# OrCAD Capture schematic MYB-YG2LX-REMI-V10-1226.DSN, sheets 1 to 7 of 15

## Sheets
1 Cover: title: SCH-MYB-YG2LX-V01; rev: V1.0; note: Cover
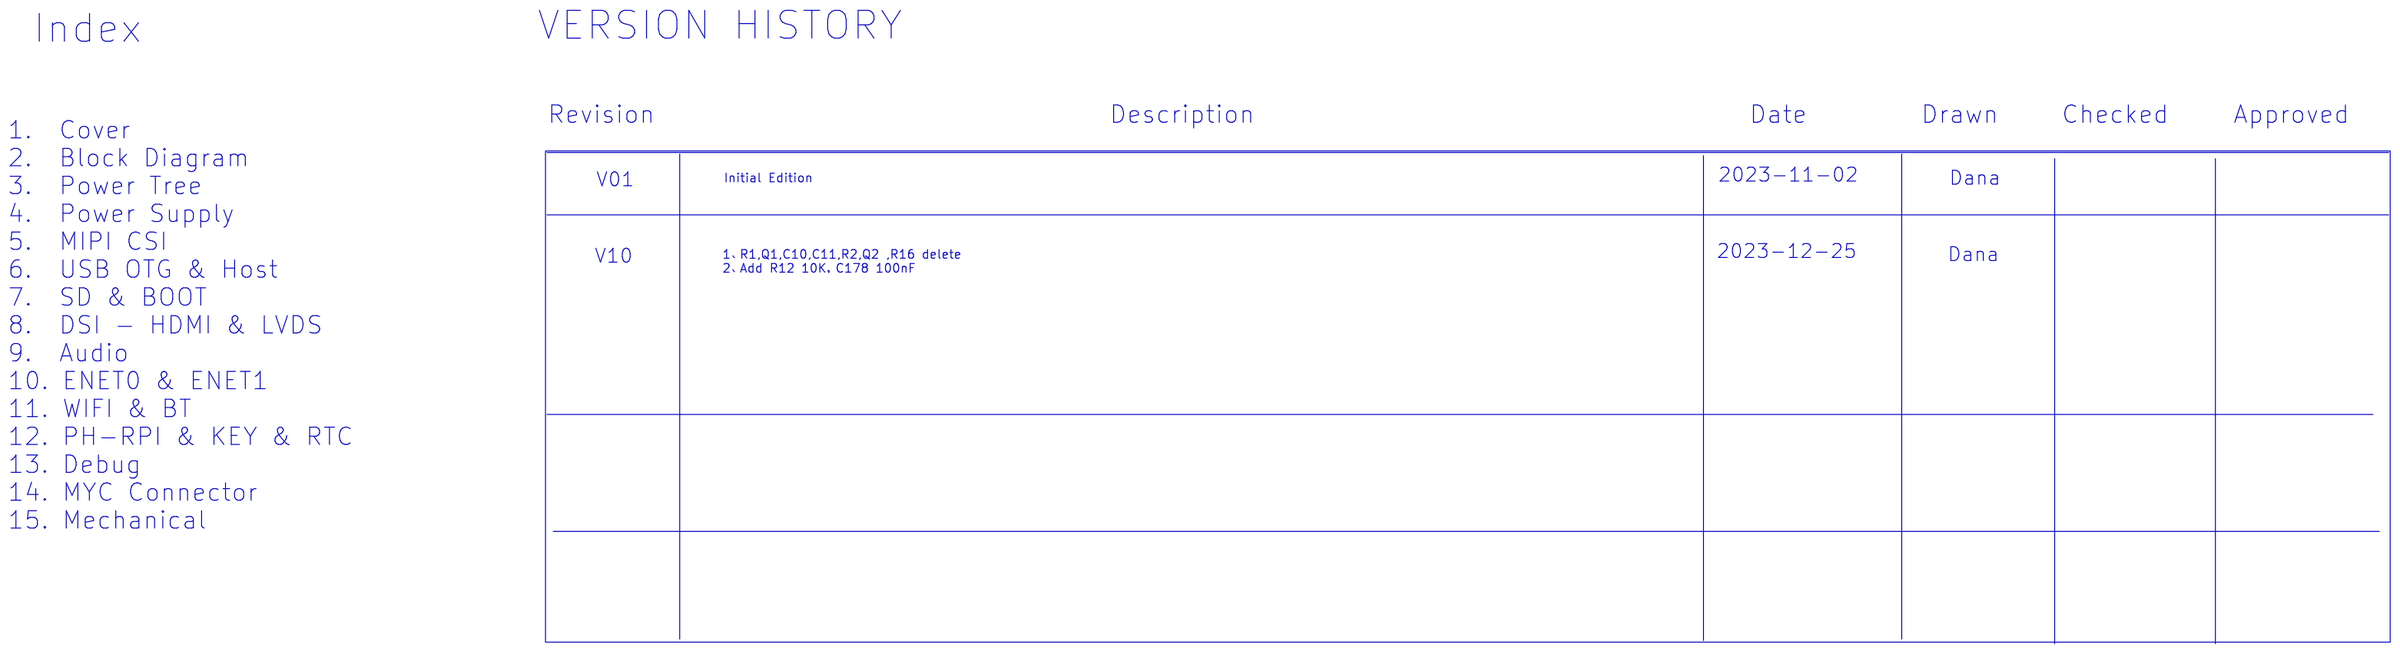
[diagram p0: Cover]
2 Block Diagram: note: Block Diagram
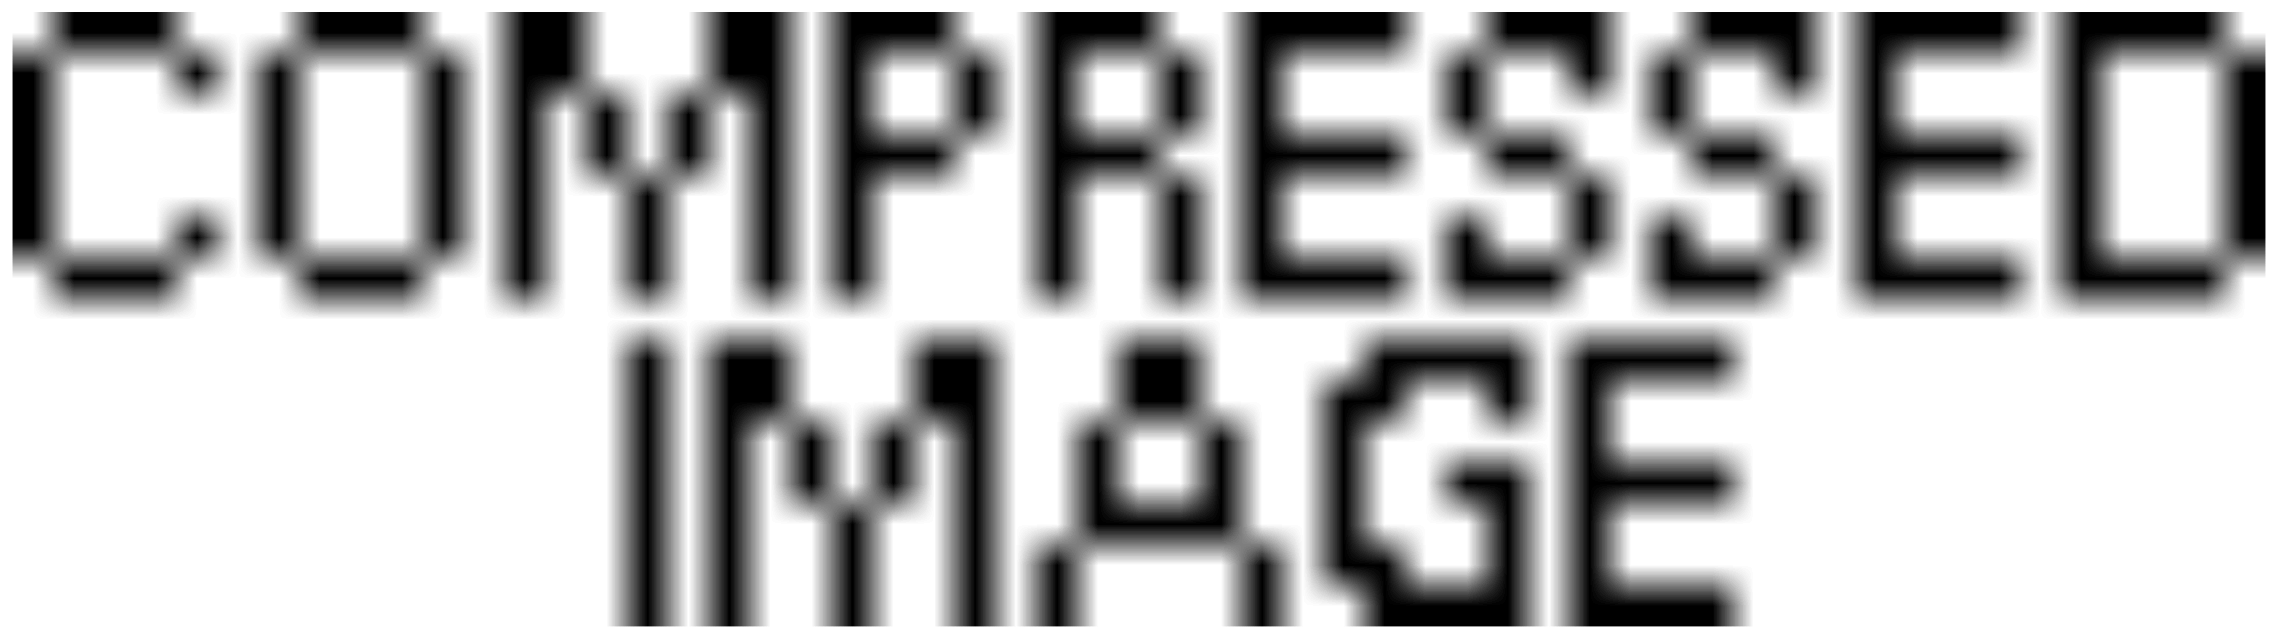
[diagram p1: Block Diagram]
3 Power Tree: note: Power Tree
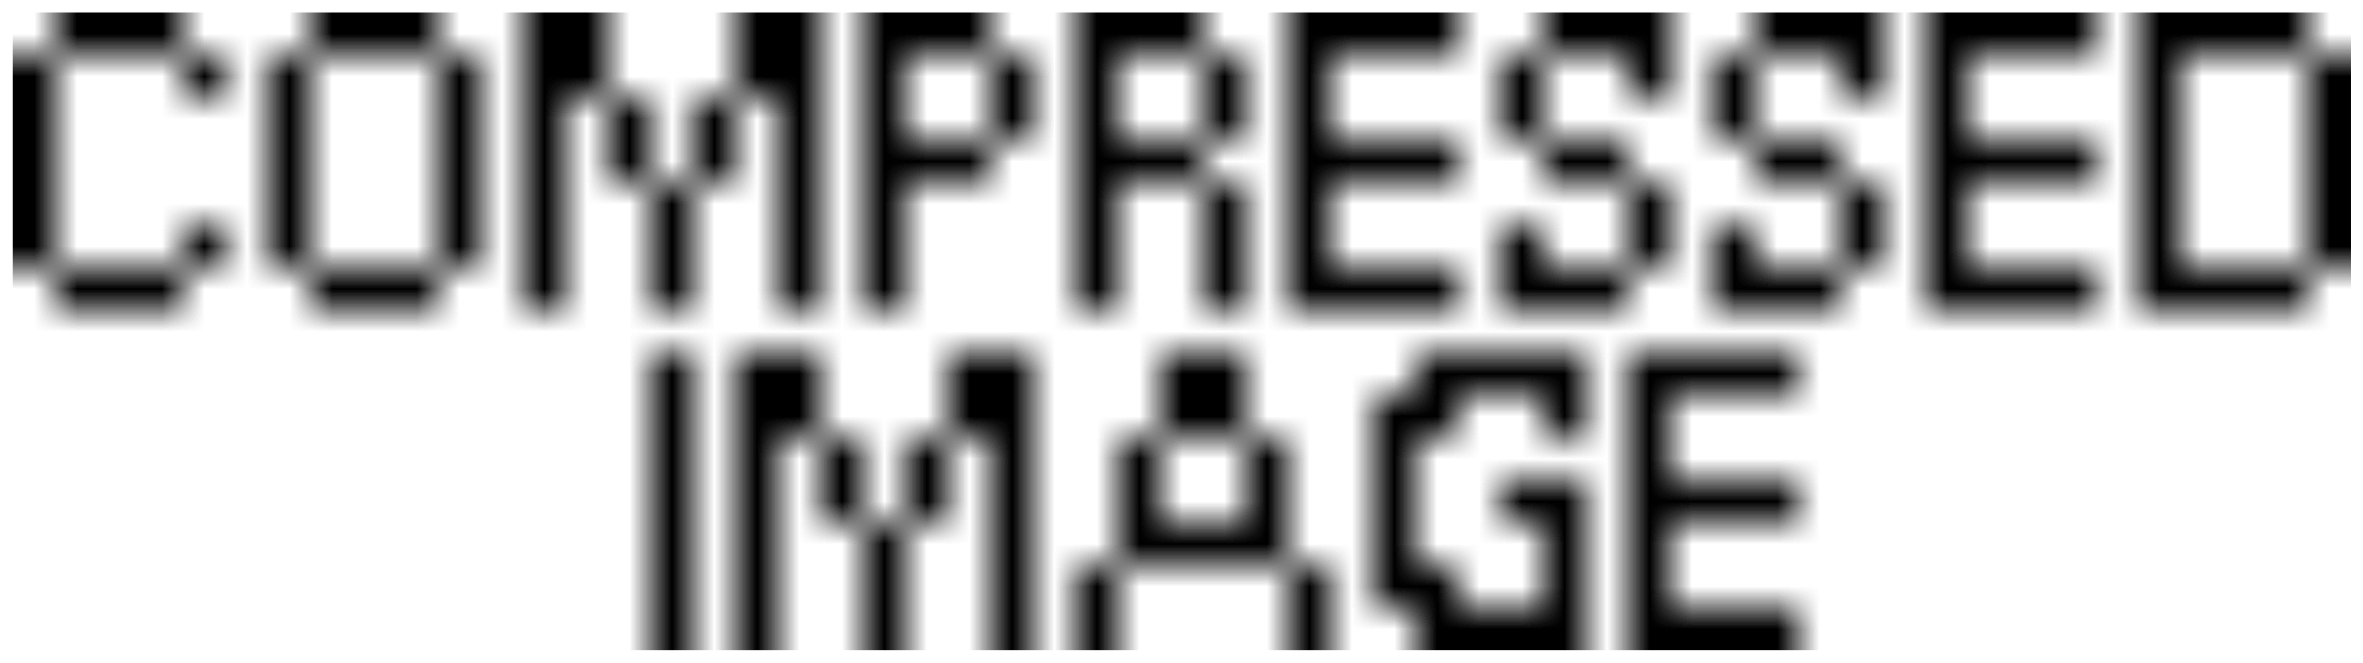
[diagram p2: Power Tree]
4 Power Supply: size A3; note: Power Supply
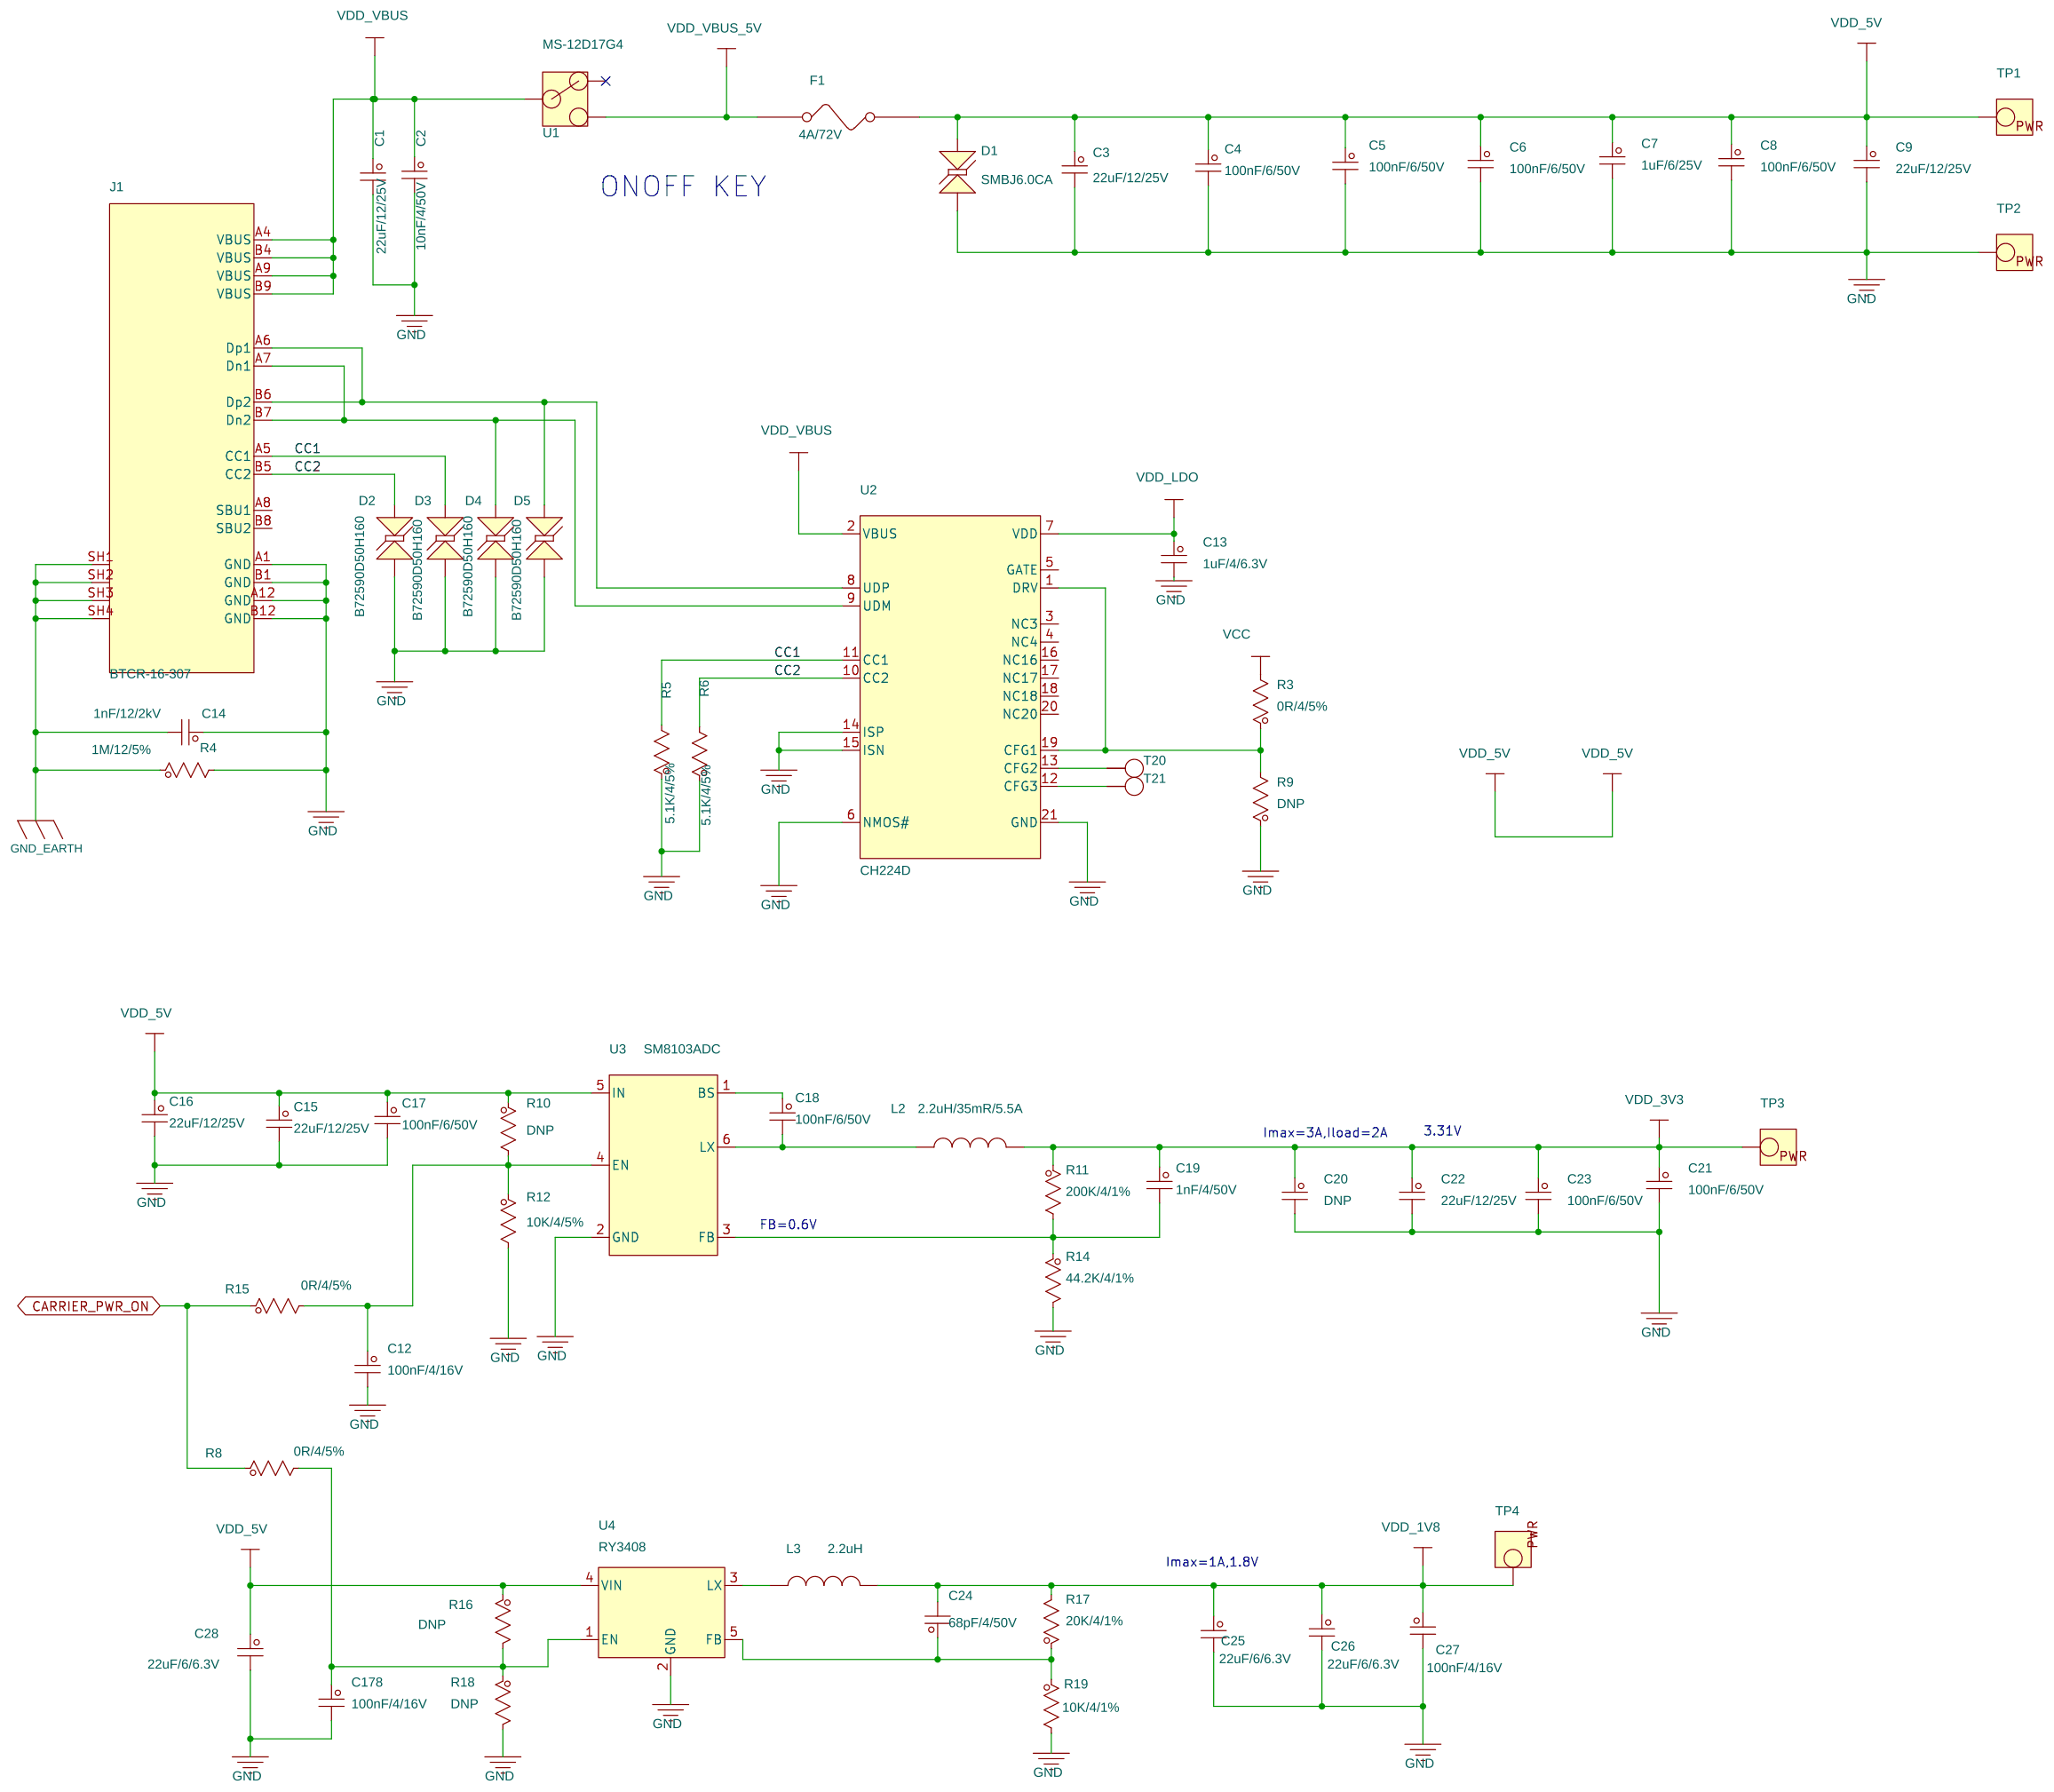
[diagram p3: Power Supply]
5 MIPI-CSI: size A3; note: CSI
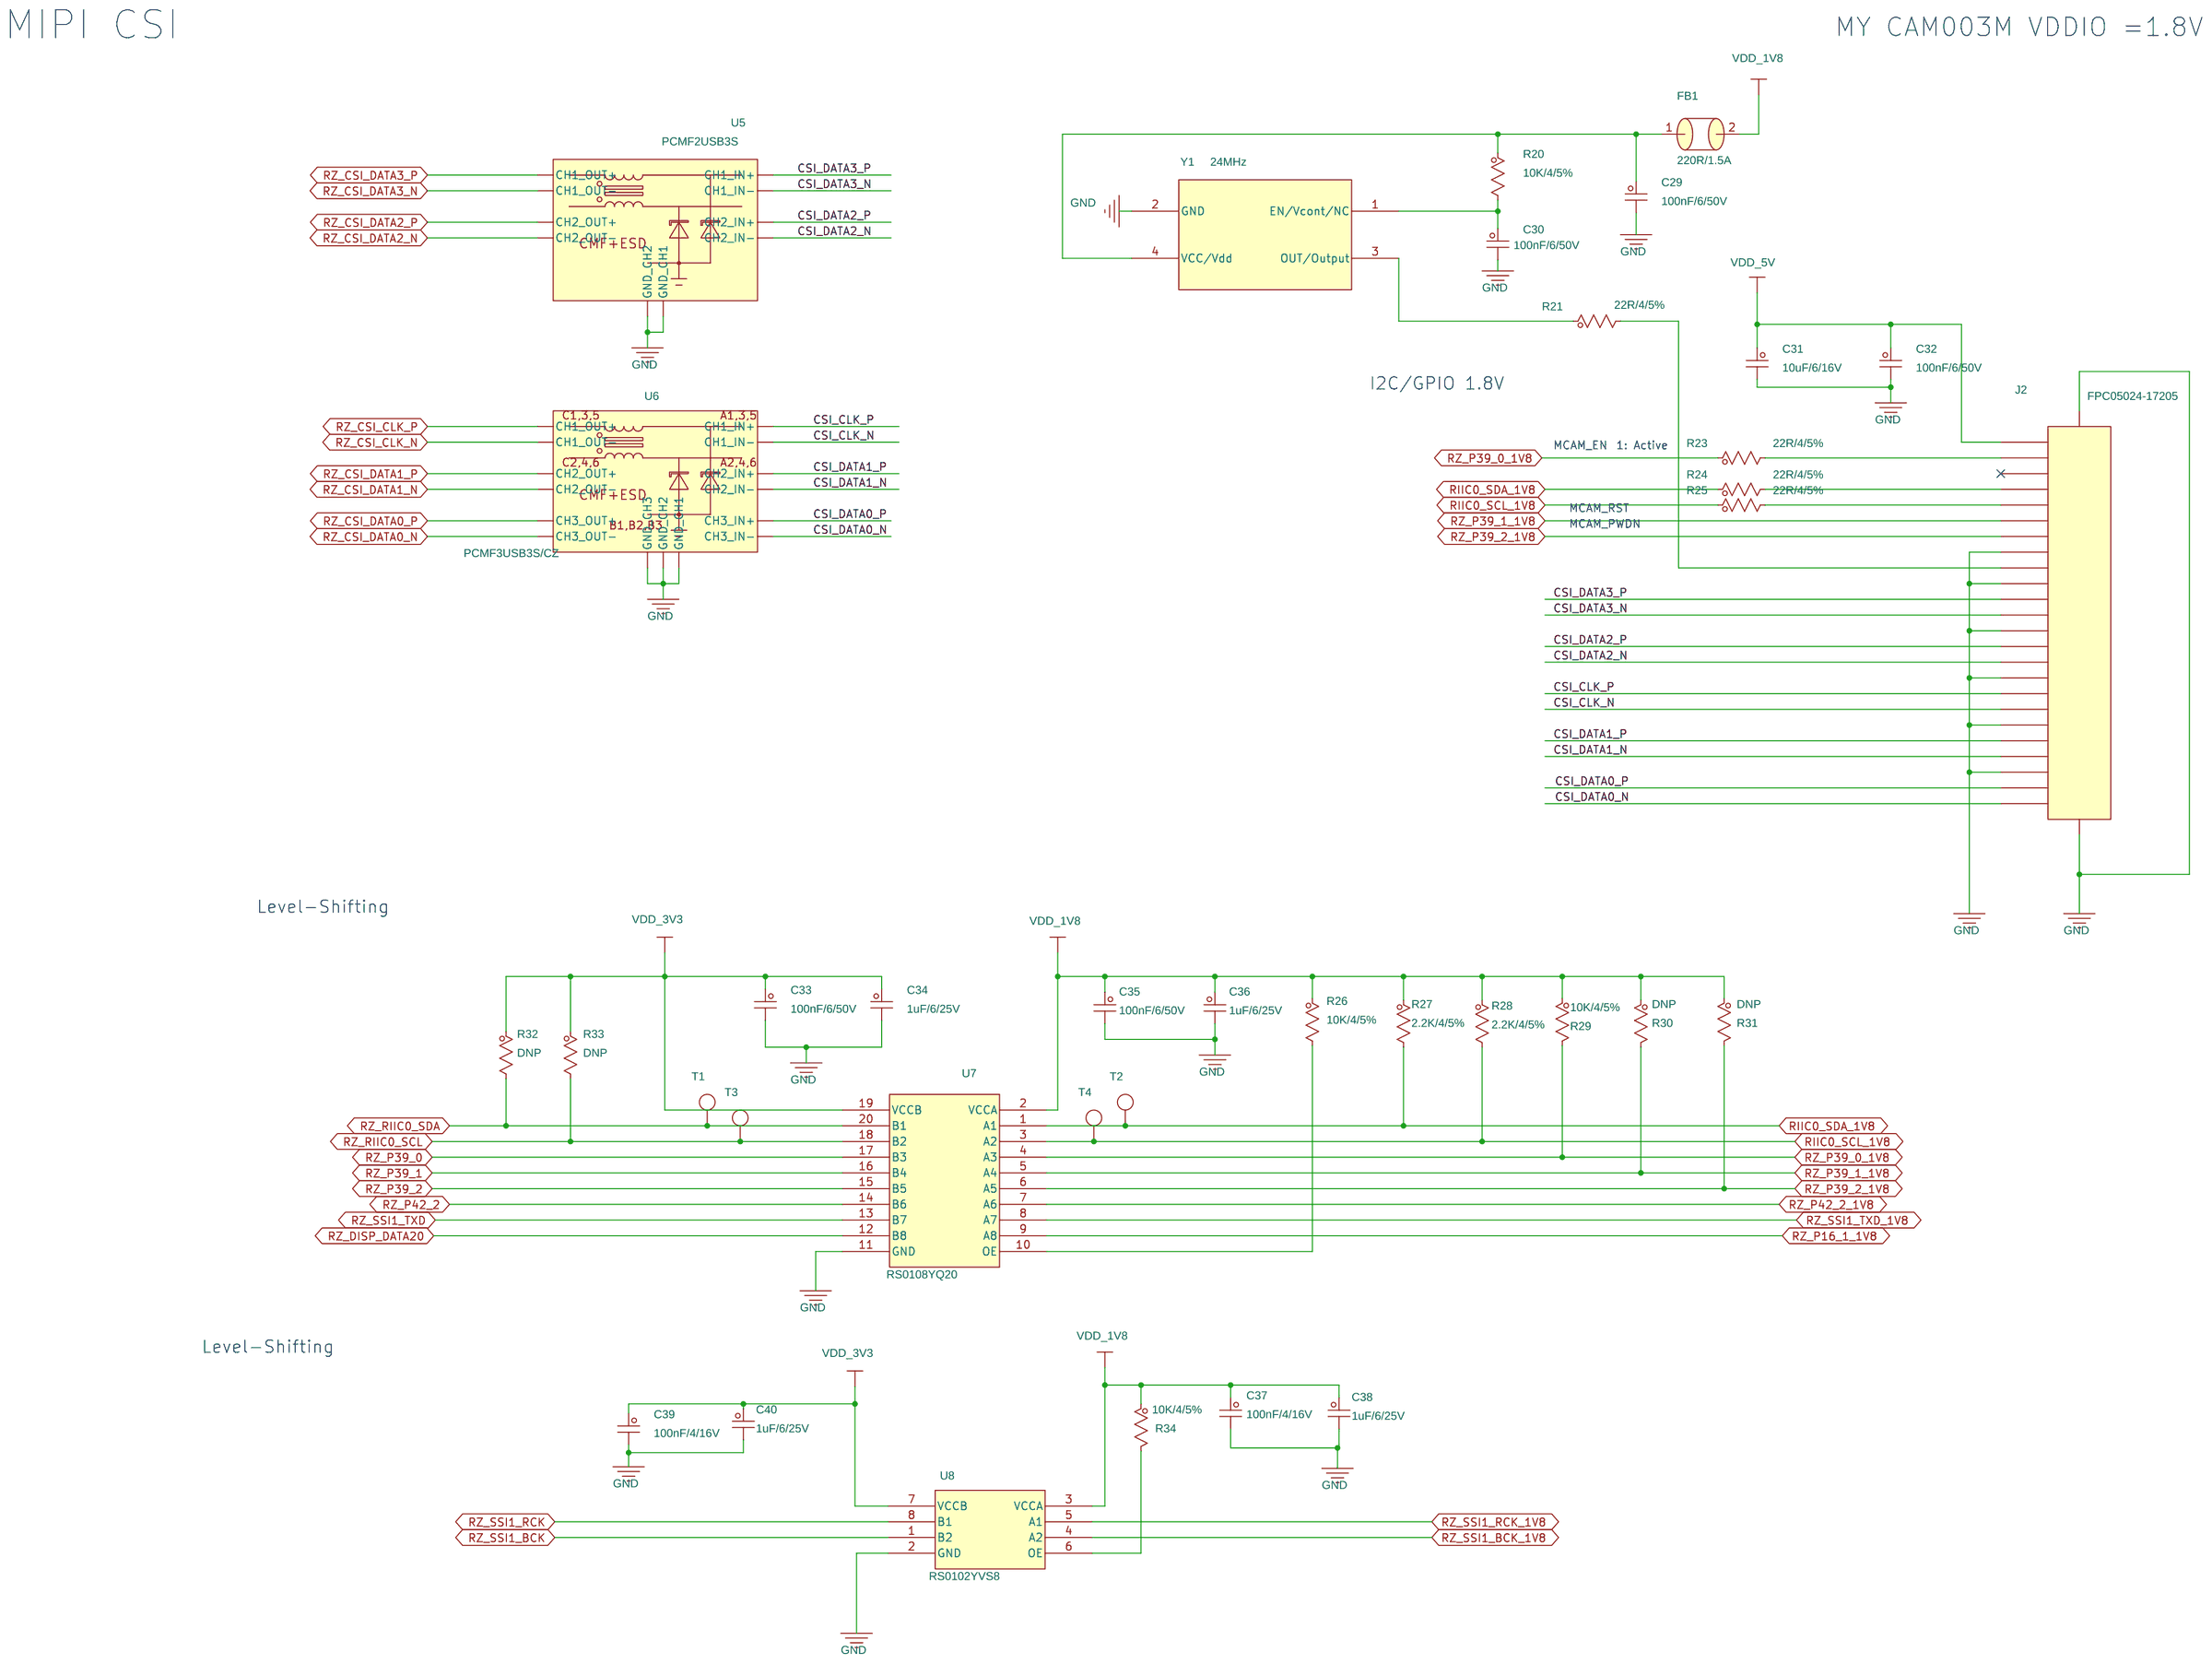
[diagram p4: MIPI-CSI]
6 USB OTG & Host: size A2; note: USB &  Debug
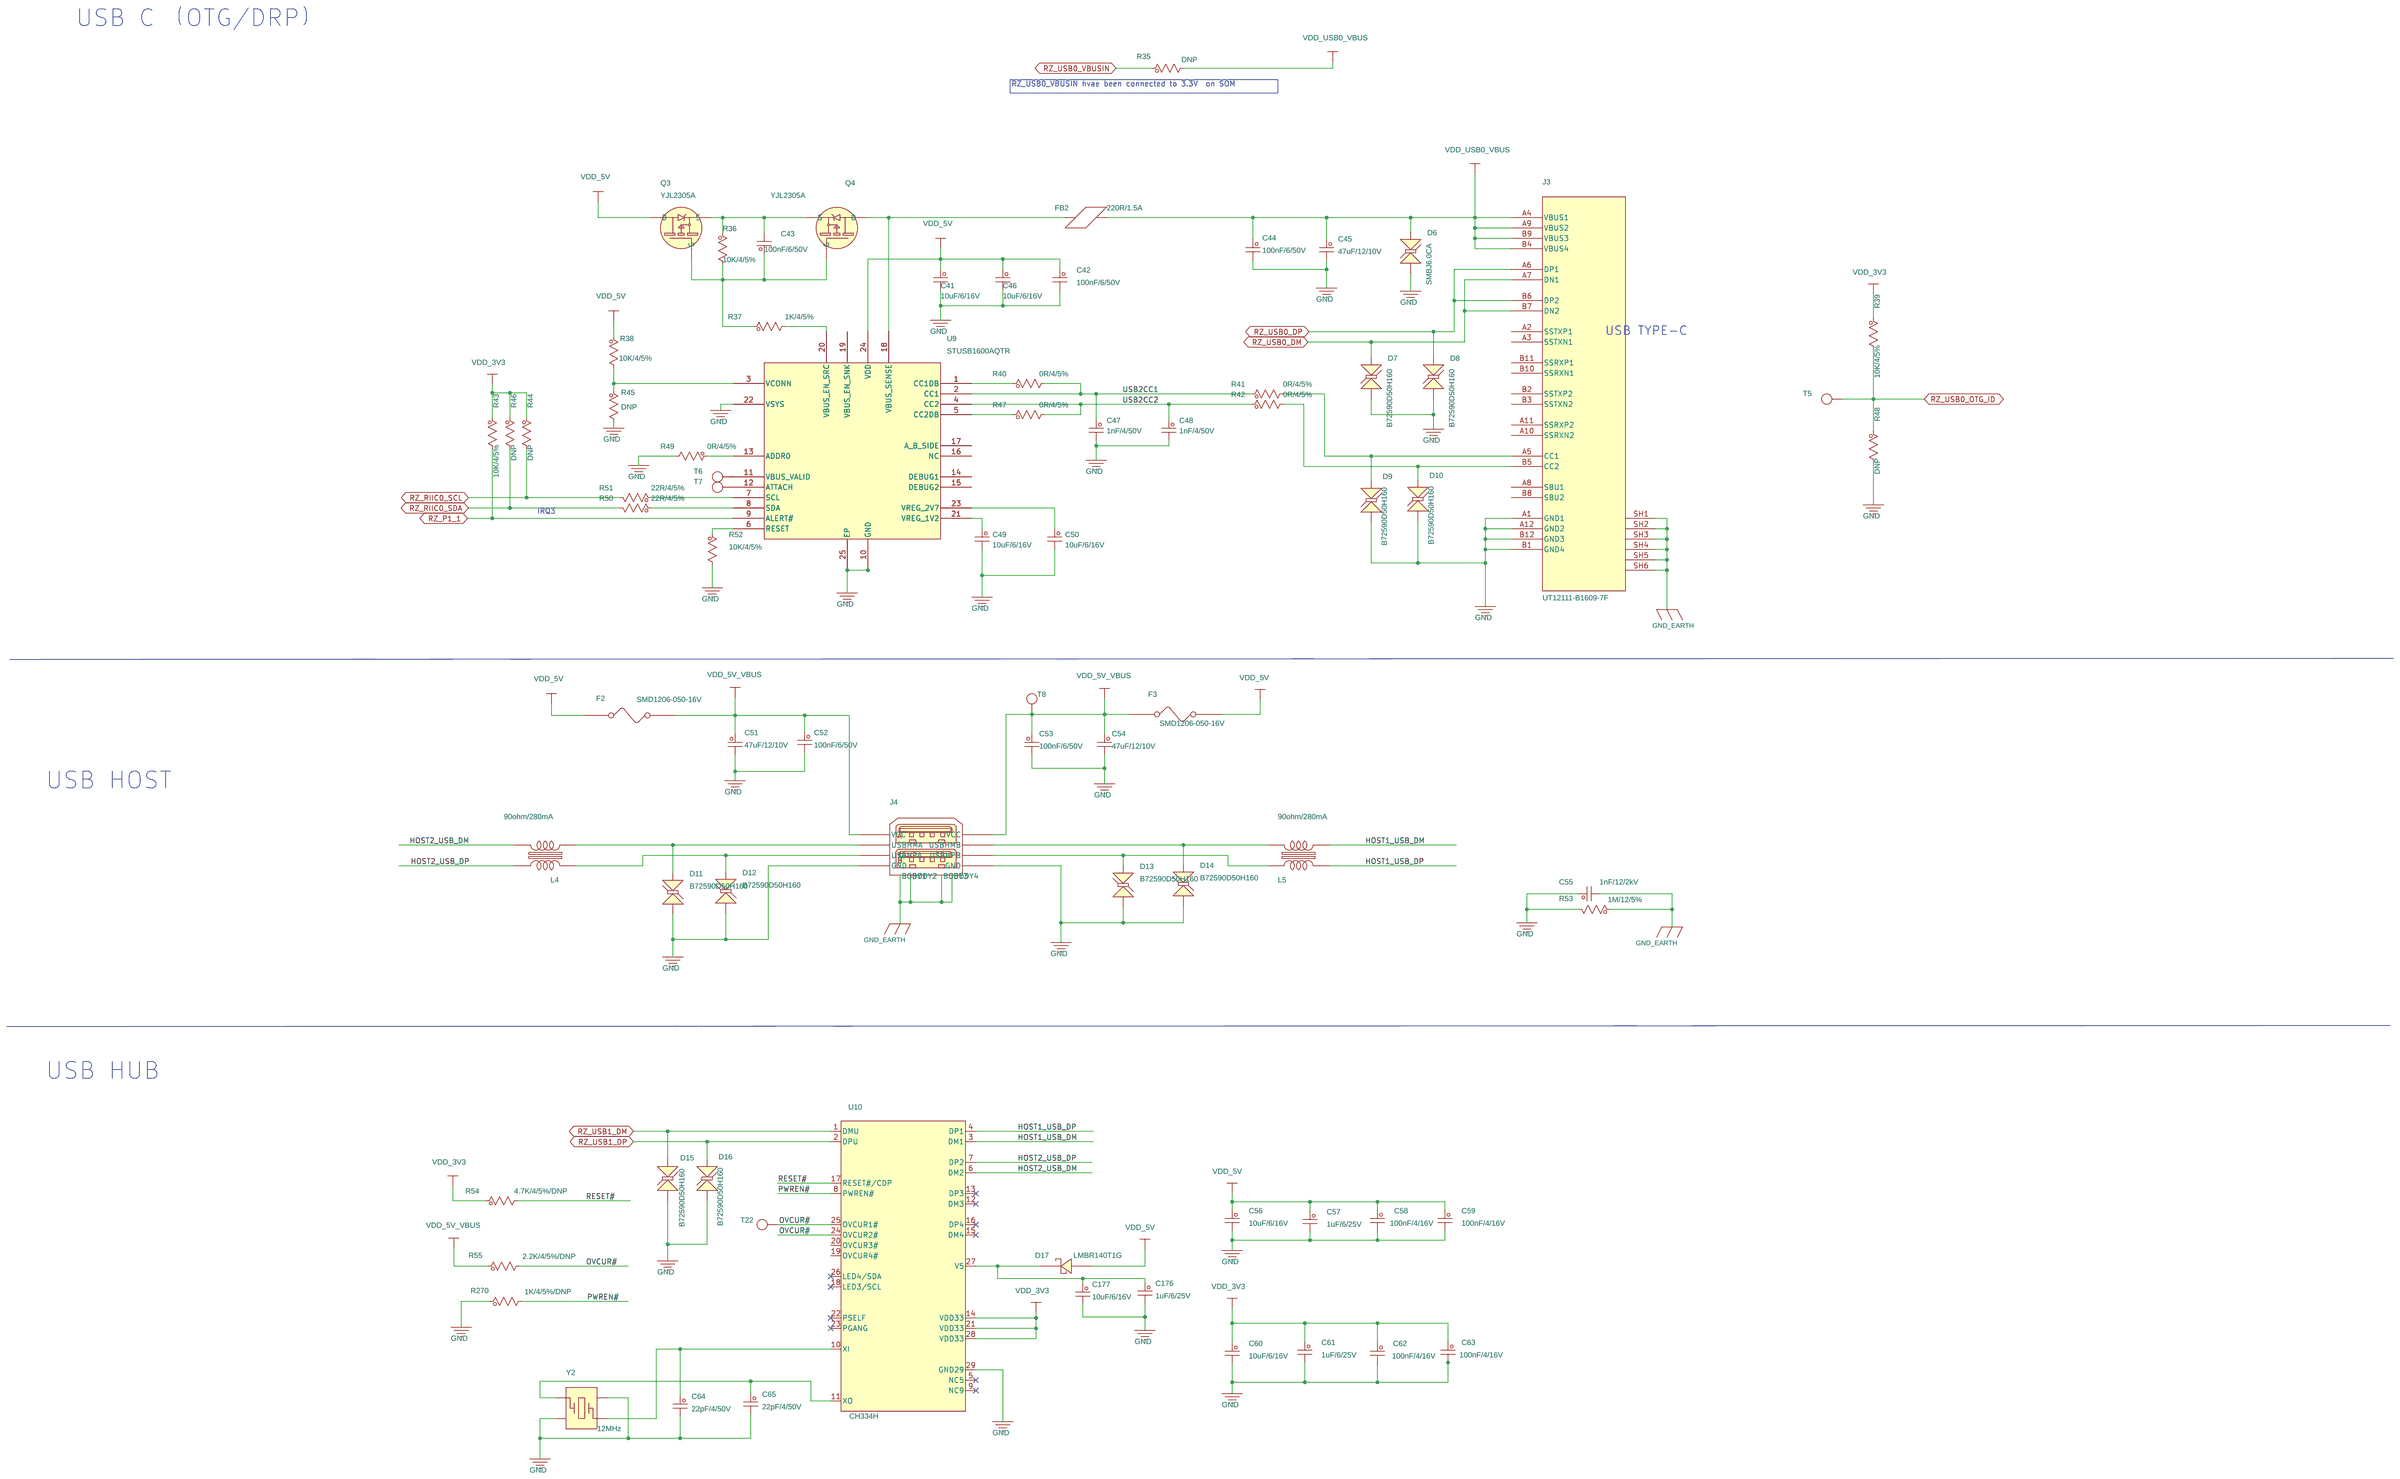
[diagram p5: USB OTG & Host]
7 SD & BOOT: size A3; note: Micro SD & Boot
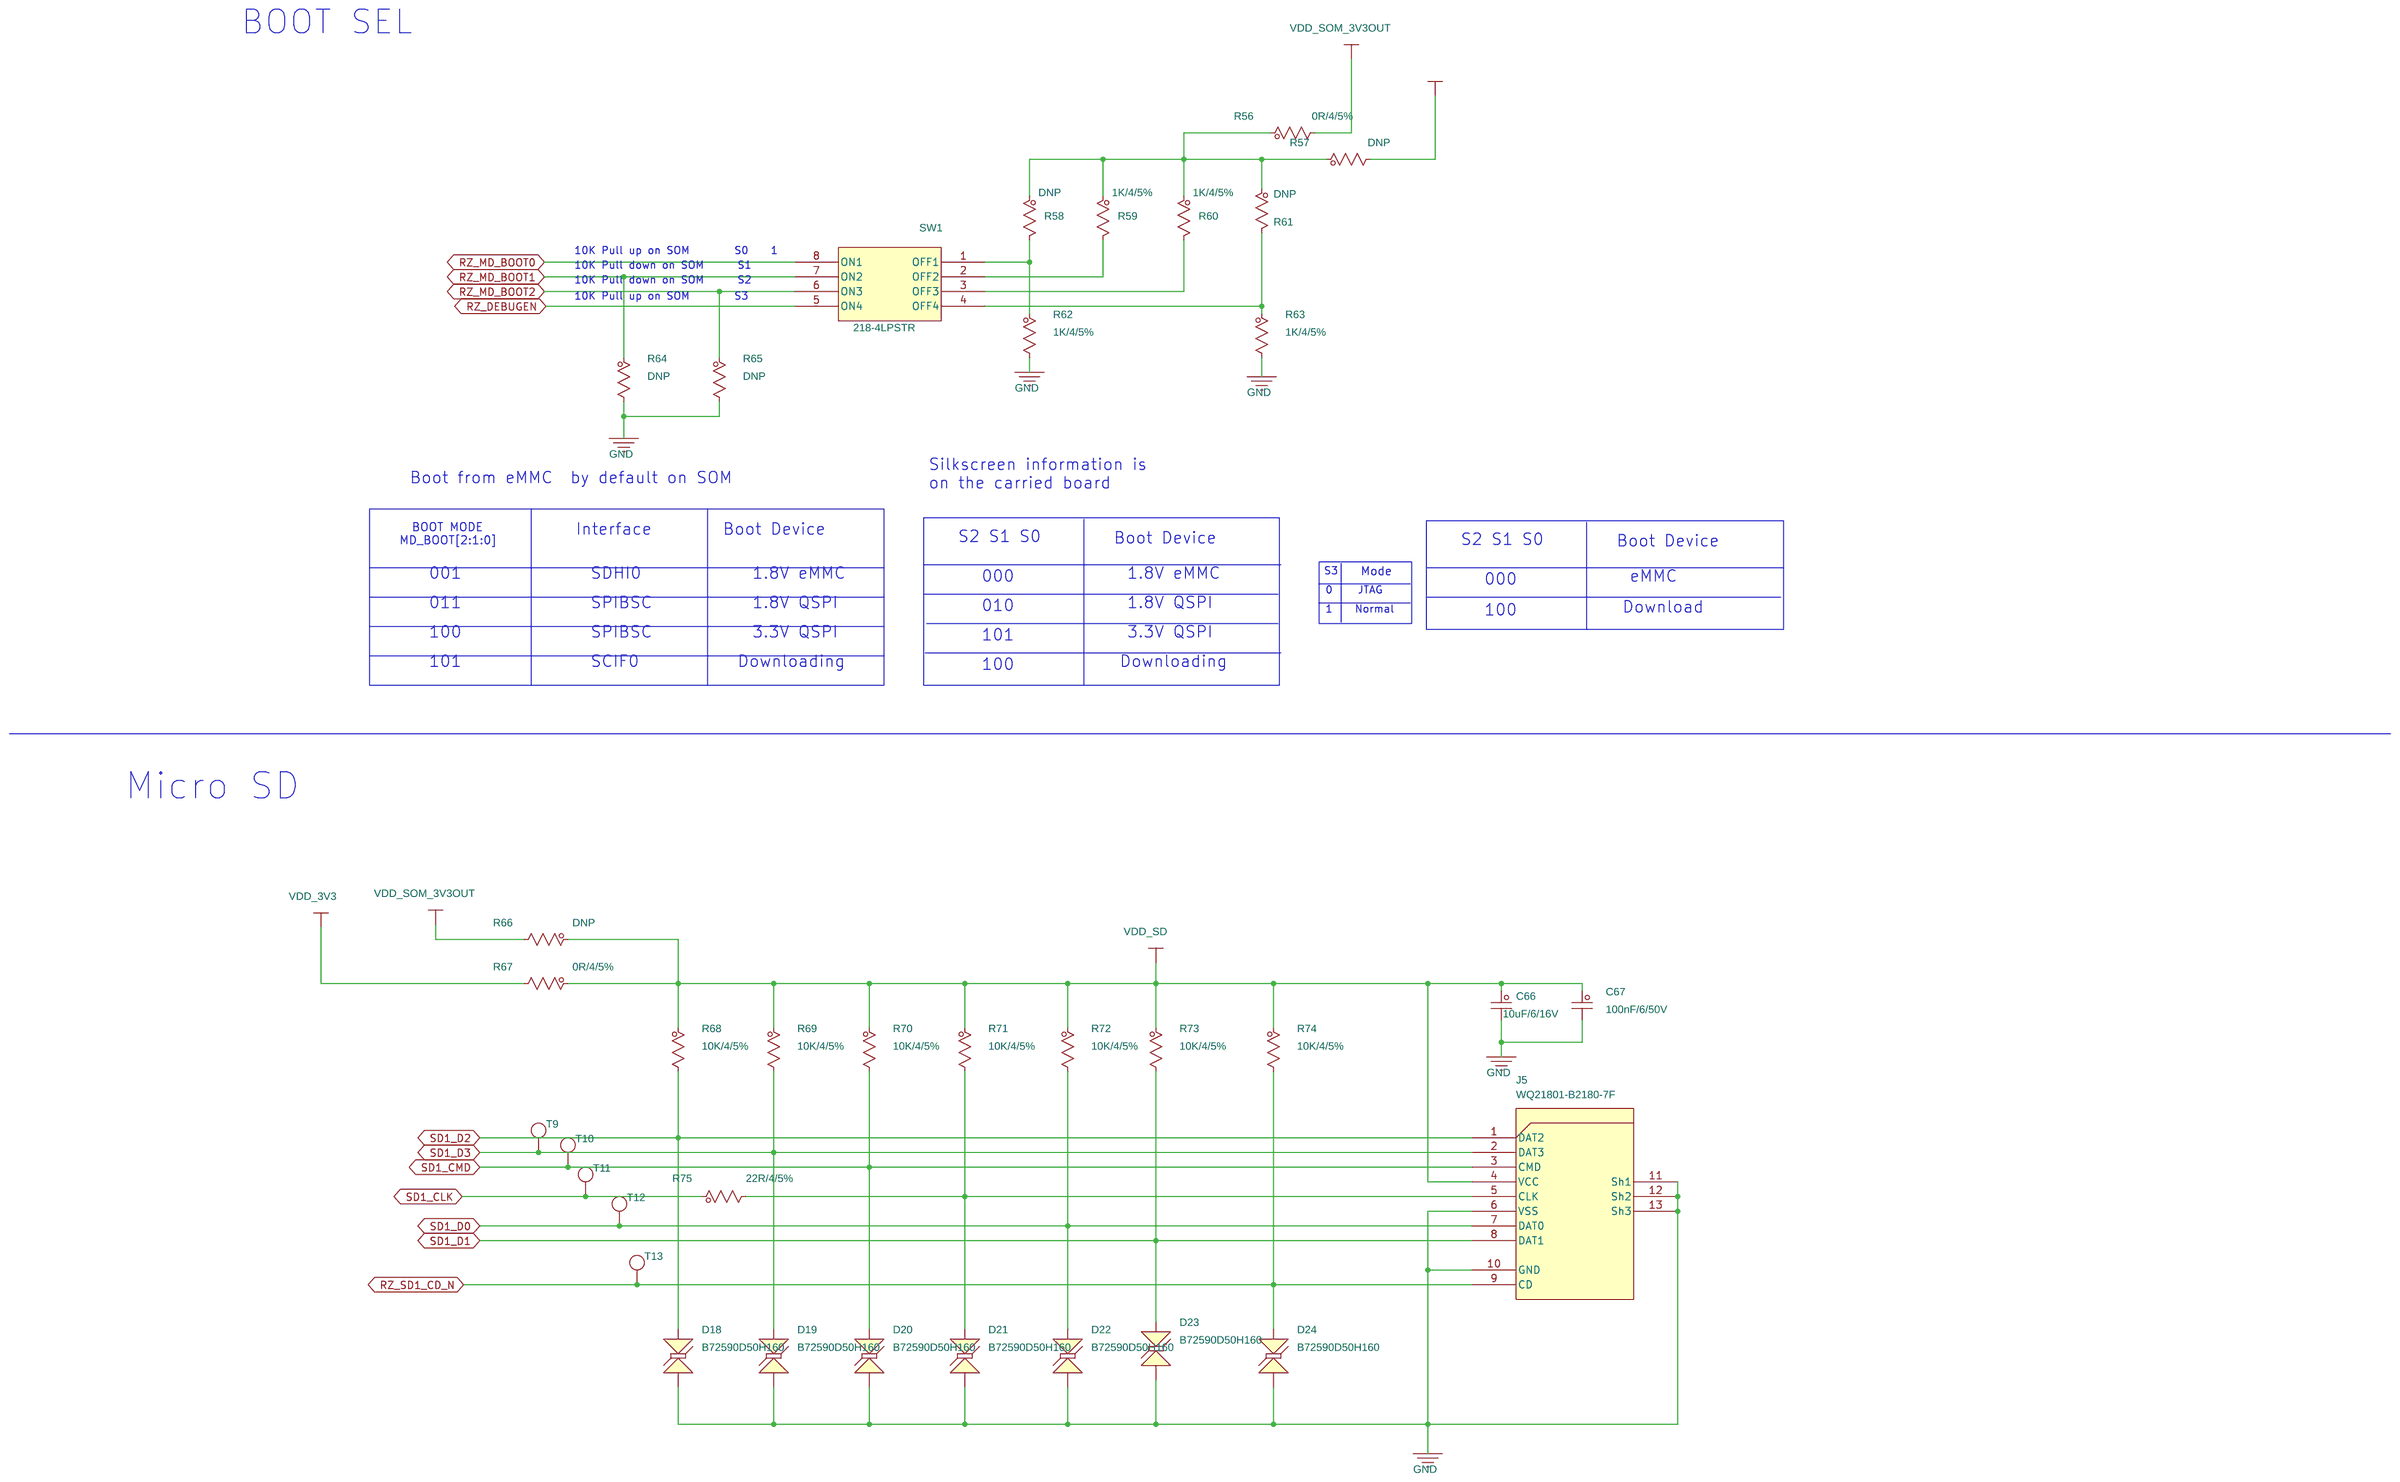
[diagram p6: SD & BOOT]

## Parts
sheet MIPI-CSI
C29  100nF/6/50V  [C0603]
C30  100nF/6/50V  [C0603]
C31  10uF/6/16V  [C0603]
C32  100nF/6/50V  [C0603]
C33  100nF/6/50V  [C0603]
C34  1uF/6/25V  [C0603]
C35  100nF/6/50V  [C0603]
C36  1uF/6/25V  [C0603]
C37  100nF/4/16V  [C0402]
C38  1uF/6/25V  [C0603]
C39  100nF/4/16V  [C0402]
C40  1uF/6/25V  [C0603]
FB1  220R/1.5A  [FB0603]
J2  FPC05024-17205  [FPC24-0_5-h]
R20  10K/4/5%  [R0402]
R21  22R/4/5%  [R0402]
R23  22R/4/5%  [R0402]
R24  22R/4/5%  [R0402]
R25  22R/4/5%  [R0402]
R26  10K/4/5%  [R0402]
R27  2.2K/4/5%  [R0402]
R28  2.2K/4/5%  [R0402]
R29  10K/4/5%  [R0402]
R30  DNP  [R0402]
R31  DNP  [R0402]
R32  DNP  [R0402]
R33  DNP  [R0402]
R34  10K/4/5%  [R0402]
T1  SMD  [test0_8-smd]
T2  SMD  [test0_8-smd]
T3  SMD  [test0_8-smd]
T4  SMD  [test0_8-smd]
U5  PCMF2USB3S  [WLCSP10]
U6  PCMF3USB3S/CZ  [WLCSP15]
U7  RS0108YQ20  [TSSOP20]
U8  RS0102YVS8  [VSSOP8]
Y1  24MHz  [3225]
sheet Power Supply
C1  22uF/12/25V  [C1206]
C2  10nF/4/50V  [C0402]
C3  22uF/12/25V  [C1206]
C4  100nF/6/50V  [C0603]
C5  100nF/6/50V  [C0603]
C6  100nF/6/50V  [C0603]
C7  1uF/6/25V  [C0603]
C8  100nF/6/50V  [C0603]
C9  22uF/12/25V  [C1206]
C12  100nF/4/16V  [C0402]
C13  1uF/4/6.3V  [C0402]
C14  1nF/12/2kV  [C1206]
C15  22uF/12/25V  [C1206]
C16  22uF/12/25V  [C1206]
C17  100nF/6/50V  [C0603]
C18  100nF/6/50V  [C0603]
C19  1nF/4/50V  [C0402]
C20  DNP  [C1206]
C21  100nF/6/50V  [C0603]
C22  22uF/12/25V  [C1206]
C23  100nF/6/50V  [C0603]
C24  68pF/4/50V  [C0402]
C25  22uF/6/6.3V  [C0603]
C26  22uF/6/6.3V  [C0603]
C27  100nF/4/16V  [C0402]
C28  22uF/6/6.3V  [C0603]
C178  100nF/4/16V  [C0402]
D1  SMBJ6.0CA  [DO-214AA]
D2  B72590D50H160  [D0402]
D3  B72590D50H160  [D0402]
D4  B72590D50H160  [D0402]
D5  B72590D50H160  [D0402]
F1  4A/72V  [F1206]
J1  BTCR-16-307  [TYPE-C-BTCF-16-307]
L2  2.2uH/35mR/5.5A  [l5_2x5_5]
L3  2.2uH  [L3X3]
R3  0R/4/5%  [R0402]
R4  1M/12/5%  [R1206]
R5  5.1K/4/5%  [R0402]
R6  5.1K/4/5%  [R0402]
R8  0R/4/5%  [R0402]
R9  DNP  [R0402]
R10  DNP  [R0402]
R11  200K/4/1%  [R0402]
R12  10K/4/5%  [R0402]
R14  44.2K/4/1%  [R0402]
R15  0R/4/5%  [R0402]
R16  DNP  [R0402]
R17  20K/4/1%  [R0402]
R18  DNP  [R0402]
R19  10K/4/1%  [R0402]
T20  SMD  [test0_8-smd]
T21  SMD  [test0_8-smd]
TP1  SMD  [HOLE-TP0_9S16]
TP2  SMD  [HOLE-TP0_9S16]
TP3  SMD  [HOLE-TP0_9S16]
TP4  SMD  [HOLE-TP0_9S16]
U1  MS-12D17G4  [SW-ms-12d17g4]
U2  CH224D  [QFN20-CH224D]
U3  SM8103ADC  [SOT23-6]
U4  RY3408  [tsot23-5]
sheet SD & BOOT
C66  10uF/6/16V  [C0603]
C67  100nF/6/50V  [C0603]
D18  B72590D50H160  [D0402]
D19  B72590D50H160  [D0402]
D20  B72590D50H160  [D0402]
D21  B72590D50H160  [D0402]
D22  B72590D50H160  [D0402]
D23  B72590D50H160  [D0402]
D24  B72590D50H160  [D0402]
J5  WQ21801-B2180-7F  [WQ21801-B2180-7F]
R56  0R/4/5%  [R0402]
R57  DNP  [R0402]
R58  DNP  [R0402]
R59  1K/4/5%  [R0402]
R60  1K/4/5%  [R0402]
R61  DNP  [R0402]
R62  1K/4/5%  [R0402]
R63  1K/4/5%  [R0402]
R64  DNP  [R0402]
R65  DNP  [R0402]
R66  DNP  [R0402]
R67  0R/4/5%  [R0402]
R68  10K/4/5%  [R0402]
R69  10K/4/5%  [R0402]
R70  10K/4/5%  [R0402]
R71  10K/4/5%  [R0402]
R72  10K/4/5%  [R0402]
R73  10K/4/5%  [R0402]
R74  10K/4/5%  [R0402]
R75  22R/4/5%  [R0402]
SW1  218-4LPSTR  [sw-2x4]
T9  SMD  [test0_8-smd]
T10  SMD  [test0_8-smd]
T11  SMD  [test0_8-smd]
T12  SMD  [test0_8-smd]
T13  SMD  [test0_8-smd]
sheet USB OTG & Host
C41  10uF/6/16V  [C0603]
C42  100nF/6/50V  [C0603]
C43  100nF/6/50V  [C0603]
C44  100nF/6/50V  [C0603]
C45  47uF/12/10V  [C1206]
C46  10uF/6/16V  [C0603]
C47  1nF/4/50V  [C0402]
C48  1nF/4/50V  [C0402]
C49  10uF/6/16V  [C0603]
C50  10uF/6/16V  [C0603]
C51  47uF/12/10V  [C1206]
C52  100nF/6/50V  [C0603]
C53  100nF/6/50V  [C0603]
C54  47uF/12/10V  [C1206]
C55  1nF/12/2kV  [C1206]
C56  10uF/6/16V  [C0603]
C57  1uF/6/25V  [C0603]
C58  100nF/4/16V  [C0402]
C59  100nF/4/16V  [C0402]
C60  10uF/6/16V  [C0603]
C61  1uF/6/25V  [C0603]
C62  100nF/4/16V  [C0402]
C63  100nF/4/16V  [C0402]
C64  22pF/4/50V  [C0402]
C65  22pF/4/50V  [C0402]
C176  1uF/6/25V  [C0603]
C177  10uF/6/16V  [C0603]
D6  SMBJ6.0CA  [do-214aa]
D7  B72590D50H160  [D0402]
D8  B72590D50H160  [D0402]
D9  B72590D50H160  [D0402]
D10  B72590D50H160  [D0402]
D11  B72590D50H160  [D0402]
D12  B72590D50H160  [D0402]
D13  B72590D50H160  [D0402]
D14  B72590D50H160  [D0402]
D15  B72590D50H160  [D0402]
D16  B72590D50H160  [D0402]
D17  LMBR140T1G  [SOD123]
F2  SMD1206-050-16V  [F1206]
F3  SMD1206-050-16V  [F1206]
FB2  220R/1.5A  [FB0603]
J3  UT12111-B1609-7F  [UT12111-B1609-7F]
J4  UB11121-8FDE-4F  [UB11121-8FDE-4F]
L4  90ohm/280mA  [indcm-sdcw2012]
L5  90ohm/280mA  [indcm-sdcw2012]
Q3  YJL2305A  [SOT-23]
Q4  YJL2305A  [SOT-23]
R35  DNP  [R0402]
R36  10K/4/5%  [R0402]
R37  1K/4/5%  [R0402]
R38  10K/4/5%  [R0402]
R39  10K/4/5%  [R0402]
R40  0R/4/5%  [R0402]
R41  0R/4/5%  [R0402]
R42  0R/4/5%  [R0402]
R43  10K/4/5%  [R0402]
R44  DNP  [R0402]
R45  DNP  [R0402]
R46  DNP  [R0402]
R47  0R/4/5%  [R0402]
R48  DNP  [R0402]
R49  0R/4/5%  [R0402]
R50  22R/4/5%  [R0402]
R51  22R/4/5%  [R0402]
R52  10K/4/5%  [R0402]
R53  1M/12/5%  [R1206]
R54  4.7K/4/5%/DNP  [R0402]
R55  2.2K/4/5%/DNP  [R0402]
R270  1K/4/5%/DNP  [R0402]
T5  SMD  [test0_8-smd]
T6  SMD  [test0_8-smd]
T7  SMD  [test0_8-smd]
T8  SMD  [test0_8-smd]
T22  SMD  [test0_8-smd]
U9  STUSB1600AQTR  [QFN24]
U10  CH334H  [QFN28_CH334DS]
Y2  12MHz  [3225]

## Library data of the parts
C4-C6 C8 C17 C18 C21 C23 C29 C30 C32 C33 C35 C44 C52 C53 C67 = Ceramic_Capacitor: Ceramic Capacitor,100nF, 50V,+/-10%, X7R,0603,Fenghua; Manufacturer: Fenghua; Manufacturer P/N: 0603B104K500NT; Myir P/N: 20401.80129; Part Type: Ceramic Capacitor; Reserve Value: 100nF; Datasheet: FENGHUA-Capacitor.pdf
C31 C56 C60 C177 = Ceramic_Capacitor: Ceramic Capacitor,10uF,16V,+/-20%,X5R,0603,Samsung; Manufacturer: Samsung; Manufacturer P/N: CL10A106MONQNC; Myir P/N: 20401.80062; Part Type: Ceramic Capacitor; Reserve Value: 10uF; Datasheet: Samsung.pdf
C7 C34 C36 C38 C40 C57 C61 C176 = Ceramic_Capacitor: Ceramic Capacitor,1uF, 25V,+/-10%,X5R,0603,Samsung; Manufacturer: Samsung; Manufacturer P/N: CL10A105KA8NNNC; Myir P/N: 20401.80063; Part Type: Ceramic Capacitor; Reserve Value: 1uF; Datasheet: Samsung.pdf
C12 C27 C37 C39 C178 = Ceramic_Capacitor: Ceramic Capacitor,100nF,16V,+/-10%,X7R,0402,Fenghua; Manufacturer: Fenghua; Manufacturer P/N: 0402B104K160NT; Myir P/N: 20401.80188; Part Type: Ceramic Capacitor; Reserve Value: 100nF; Datasheet: FENGHUA-Capacitor.pdf
FB1 = Ferrite_Bead: Ferrite Bead,220R@100Mhz,1.5A,+/-25%,SMD,0603,Fenghua; Manufacturer: Fenghua; Manufacturer P/N: CBM160808U221T; Myir P/N: 20601.80007; Part Type: Ferrite Bead; Reserve Value: 220R; Datasheet: CBM160808U221T.pdf
J2 = FPC24: FPC Connector,24pin,0.5mm pitch,Dual-sided Contact Models, Operating temperature range from–45~85℃,Atom; Manufacturer: Atom; Myir P/N: 21106.00017; Part Type: FPC Connector; Datasheet: FPC_Atom.pdf
R20 R26 = RESISTER: Thick Film Resistor,10K,+/-5%,1/16W,-55°C ~ 155°C,SMD,0402,Fenghua; Manufacturer: Fenghua; Manufacturer P/N: RC-02W103JT; Myir P/N: 20301.00199; Part Type: Thick Film Resistor; Reserve Value: 10K; Datasheet: FH规格书_2018-07-30.pdf
R21 R23-R25 = RESISTER: Thick Film Resistor,22R,+/-5%,1/16W,-55°C ~ 155°C,SMD,0402,Fenghua; Manufacturer: Fenghua; Manufacturer P/N: RC-02W220JT; Myir P/N: 20301.00187; Part Type: Thick Film Resistor; Reserve Value: 22R; Datasheet: FH规格书_2018-07-30.pdf
R27 R28 R32 R33 = RESISTER: Thick Film Resistor,2.2K,+/-5%,1/16W,-55°C ~ 155°C,SMD,0402,Fenghua; Manufacturer: Fenghua; Manufacturer P/N: RC-02W222JT; Myir P/N: 20301.00195; Part Type: Thick Film Resistor; Reserve Value: 2.2K; Datasheet: FH规格书_2018-07-30.pdf
R29-R31 R34 R58 R61 R68-R74 = Resister: Thick Film Resistor,10K,+/-5%,1/16W,-55°C ~ 155°C,SMD,0402,Fenghua; Manufacturer: Fenghua; Manufacturer P/N: RC-02W103JT; Myir P/N: 20301.00199; Part Type: Thick Film Resistor; Reserve Value: 10K; Datasheet: FHsheet_2018-07-30.PDF
T1-T13 T20-T22 = TP: DESIG: testing PAD; FAB: NA; REF: NA; VAL: NOT POPULATED
U5 = PCMF2USB3S: IC,Common-mode EMI filter for 2 channels with integrated ESD protection,SMD,WLCSP10,PF2S,NXP; Manufacturer: NXP; Myir P/N: 20114.00011; Part Type: Protection; Datasheet: PCMFxUSB3S.pdf
U6 = PCMF3USB3S: IC,Common-mode EMI filter for 3 channels with integrated ESD protection,SMD,WLCSP15,PF3S,NXP; Manufacturer: NXP; Myir P/N: 20114.00010; Part Type: Protection; Datasheet: PCMFxUSB3S.pdf
U7 = TXB0108: IC,8-Bit Bidirectional Voltage-Level Translator for Open-Drain and Push-Pull Applications,SMD,TSSOP20,Runic; Manufacturer: Runic; Myir P/N: 20105.00031; Part Type: Logic; RP1 Manufacturer P/N: TXS0108EPWR; RP1 Myir P/N: 20105.80003; Datasheet: RS0108.pdf
U8 = TXS0102DCT: IC,2-Bit Bidirectional Voltage-Level Translator for Open-Drain and Push-Pull Application,SMD,VSSOP8,Runic; Manufacturer: Runic; Myir P/N: 20105.00030; Part Type: Logic; Datasheet: RS0102.pdf
Y1 = Oscillator_4P: Oscillator,24Mhz,+/- 25ppm,3.3V,-40~85℃,3225,SMD,Hosonic; Manufacturer: Hosonic; Manufacturer P/N: D3SX24E000005E; Myir P/N: 20902.80014; Part Type: Oscillator; Datasheet: 天二电子 201203 D3SX24E000005E V1.0.pdf
C1 = Ceramic_Capacitor: Ceramic Capacitor,22uF,+/-10%,X5R,25V,SMD,1206,Samsung; Manufacturer: Samsung; Manufacturer P/N: CL31A226KAHNNNE; Myir P/N: 20401.00064; Part Type: Ceramic Capacitor; Reserve Value: 22uF; Datasheet: Samsung.pdf
C2 = Ceramic_Capacitor: Ceramic Capacitor,10nF,50V,+/-10%,X7R,0402,Fenghua; Manufacturer: Fenghua; Manufacturer P/N: 0402B103K500NT; Myir P/N: 20401.80103; Part Type: Ceramic Capacitor; Reserve Value: 10nF; Datasheet: FENGHUA-Capacitor.pdf
C3 C9 C15 C16 C22 = Ceramic_Capacitor: Ceramic Capacitor,22uF,25V,+/-10%,X5R,1206,Samsung; Manufacturer: Samsung; Manufacturer P/N: CL31A226KAHNNNE; Myir P/N: 20401.00064; Part Type: Ceramic Capacitor; Reserve Value: 22uF; Datasheet: Samsung.pdf
C13 = Ceramic_Capacitor: Ceramic Capacitor,1uF,6.3V,+/-20%,X5R,SMD,0402,Reel,Fenghua; Manufacturer: Fenghua; Manufacturer P/N: 0402X105M6R3NT; Myir P/N: 20401.00102; Part Type: Ceramic Capacitor; Reserve Value: 1uF; Datasheet: FENGHUA-Capacitor.pdf
C14 = Ceramic_Capacitor: Ceramic Capacitor,1nF,+/-10%,2kV,X7R,SMD,1206,Fenghua; Manufacturer: Fenghua; Manufacturer P/N: 1206B102K202NT; Myir P/N: 20401.00078; Part Type: Ceramic Capacitor; Reserve Value: 1nF; Datasheet: FENGHUA-Capacitor.pdf
C19 = Ceramic_Capacitor: Ceramic Capacitor,1nF,50V,+/-10%,X7R,0402,Fenghua; Manufacturer: Fenghua; Manufacturer P/N: 0402B102K500NT; Myir P/N: 20401.80096; Part Type: Ceramic Capacitor; Reserve Value: 1nF; Datasheet: FENGHUA-Capacitor.pdf
C20 C45 C51 C54 = Ceramic_Capacitor: Ceramic Capacitor,47uF,10V,+/-20%,X5R,1206,Samsung; Manufacturer: Samsung; Manufacturer P/N: CL31A476MPHNNNE; Myir P/N: 20401.80106; Part Type: Ceramic Capacitor; Reserve Value: 47uF; Datasheet: Samsung.pdf
C24 = Ceramic_Capacitor: Ceramic Capacitor,68pF,50V,+/-5%,C0G,0402,Fenghua; Manufacturer: Fenghua; Manufacturer P/N: 0402CG680J500NT; Myir P/N: 20401.80102; Part Type: Ceramic Capacitor; Reserve Value: 68pF; Datasheet: FENGHUA-Capacitor.pdf
C25 C26 C28 = Ceramic_Capacitor: Ceramic Capacitor,22uF,+/-20%,6.3V,X5R,SMD,0603,Samsung; Manufacturer: Samsung; Manufacturer P/N: CL10A226MQ8NRNC; Myir P/N: 20401.00086; Part Type: Ceramic Capacitor; Reserve Value: 22uF; Datasheet: Samsung.pdf
D1 D6 = TVS_Diode: Diode, TVS Bi-Dir 6V 600W, DO-214AA(SMB); Manufacturer: UN; Myir P/N: 20701.00028; Part Type: Diode; Datasheet: SMBJ6.0C.pdf
D2-D5 D7-D16 D18-D24 = TVS_Diode: Diode,TVS,5.6VDC,SMD,D0402,TDK; Manufacturer: TDK; Myir P/N: 20701.00001; Part Type: Diode; Datasheet: B72590D0050H160.pdf
F1 = Fuse: Fuse,Resettable 4A 75V,SMD 1206,TLC; Manufacturer: TLC; Manufacturer P/N: F12F4; Myir P/N: 20801.00014; Part Type: Resettable Fuse; Reserve Value: 4A; Datasheet: F12F Series.pdf
J1 = USB616FC-C2014216: Connector,USB C,16Pin,-25℃~＋85℃,SMD,Reel,GDZ; Manufacturer: GDZ; Myir P/N: 21107.00026; Part Type: USB Connector; Datasheet: BTCF-16-307TYPE-C.pdf
L2 = Inductor: Power Inductor,2.2uH 20%,35mOhm 5.5A ,SMD 5.4*5.2*2.8mm; Manufacturer: Vcoil; Manufacturer P/N: MPH0530-2R2M; Myir P/N: 20501.00020; Part Type: Power Inductor; RP1 Manufacturer P/N: MWSA0503S-2R2MT; RP1 Myir P/N: 20501.00040; Reserve Value: 2.2uH; Datasheet: MPH-Inductor.pdf
L3 = Inductor: Power Inductor,2.2uH,+/-20,SPH,3.0*3.0*1.2mm,SMD,Sunlord; Manufacturer: Sunlord; Manufacturer P/N: SPH3012H2R2MT; Myir P/N: 20501.00034; Part Type: Power Inductor; Datasheet: SPH series of SMD Power Inductor.pdf
R3 R8 = Resister: Thick Film Resistor,0R,+/-5%,1/16W,-55℃~155℃,SMD,0402,Fenghua; Manufacturer: Fenghua; Manufacturer P/N: RC-02000JT; Myir P/N: 20301.00186; Part Type: Thick Film Resistor; Reserve Value: 0R; Datasheet: FHsheet-20230524.pdf
R4 = Resister: Thick Film Resistor,1M,+/-5%,1/4W,-55°C ~ 155°C,SMD,1206,Fenghua; Manufacturer: Fenghua; Manufacturer P/N: RS-06K105JT; Myir P/N: 20301.00226; Part Type: Thick Film Resistor; Reserve Value: 1M; Datasheet: FH规格书_2018-07-30.pdf
R5 R6 = Resister: Thick Film Resistor,5.1K,±5%,1/16W,-55~+155℃,0402,Fenghua; Manufacturer: Fenghua; Manufacturer P/N: RC-02K512JT; Myir P/N: 20301.80358; Part Type: Thick Film Resistor; Reserve Value: 5.1K; Datasheet: FHsheet-20230524.pdf
R9 R12 R18 = Resister: Thick Film Resistor,10K,+/-5%,1/16W,-55℃~155℃,SMD,0402,Fenghua; Manufacturer: Fenghua; Manufacturer P/N: RC-02K103JT; Myir P/N: 20301.00199; Part Type: Thick Film Resistor; Reserve Value: 10K; Datasheet: FHsheet-20230524.pdf
R10 = Resister: Thick Film Resistor,100K,+/-5%,,1/16W,-55°C ~ 155°C,SMD,0402,Fenghua; Manufacturer: Fenghua; Manufacturer P/N: RC-02W104JT; Myir P/N: 20301.00210; Part Type: Thick Film Resistor; Reserve Value: 100K; Datasheet: FH规格书_2018-07-30.pdf
R11 = Resister: Thick Film Resistor,200K,+/- 1%,1/16W,-55°C ~ 155°C,SMD,0402,Fenghua; Manufacturer: Fenghua; Manufacturer P/N: RC-02W2003FT; Myir P/N: 20301.80390; Part Type: Thick Film Resistor; Reserve Value: 200K; Datasheet: FH规格书_2018-07-30.pdf
R14 = Resister: Thick Film Resistor,44.2k,+/-1%,1/16W,-55°C ~ 155°C,SMD,0402,Fenghua; Manufacturer: Fenghua; Manufacturer P/N: RC-02W4422FT; Myir P/N: 20301.00203; Part Type: Thick Film Resistor; Reserve Value: 44.2k; Datasheet: FH规格书_2018-07-30.pdf
R15 R35 R66 R67 = Resister: Thick Film Resistor,0R,+/-5%,1/16W,-55°C ~ 155°C,SMD,0402,Fenghua; Manufacturer: Fenghua; Manufacturer P/N: RC-02000JT; Myir P/N: 20301.00186; Part Type: Thick Film Resistor; Reserve Value: 0R; Datasheet: FHsheet_2018-07-30.PDF
R16 R54 = Resister: Thick Film Resistor,4.7K,+/-5%,1/16W,-55℃~155℃,SMD,0402,Fenghua; Manufacturer: Fenghua; Manufacturer P/N: RC-02K472JT; Myir P/N: 20301.80393; Part Type: Thick Film Resistor; Reserve Value: 4.7K; Datasheet: FHsheet-20230524.pdf
R17 = Resister: Thick Film Resistor,20K,+/-1%,1/16W,-55℃~155℃,SMD,0402,Fenghua; Manufacturer: Fenghua; Manufacturer P/N: RC-02K2002FT; Myir P/N: 20301.00201; Part Type: Thick Film Resistor; Reserve Value: 20K; Datasheet: FHsheet-20230524.pdf
R19 = Resister: Thick Film Resistor,10K,+/-1%,1/16W,-55℃~155℃,SMD,0402,Fenghua; Manufacturer: Fenghua; Manufacturer P/N: RC-02K1002FT; Myir P/N: 20301.80394; Part Type: Thick Film Resistor; Reserve Value: 10K; Datasheet: FHsheet-20230524.pdf
TP1-TP4 = TP_7: DESIG: testing PAD; FAB: NA; REF: NA; VAL: NOT POPULATED
U1 = MS-12D17G4: Switch, Slide Switches 4mm Pitch,3Pin,Straight,black,SMD; Manufacturer: HUANSHENG; Myir P/N: 21203.00006; Part Type: Switch; Datasheet: MS-12D17.pdf
U2 = CH224D: IC,USB PD and other fast charging protocol power receiving chip ch224,QFN20,SMD,WCH; Manufacturer: WCH; Myir P/N: 20115.80094; Part Type: Interface; Datasheet: CH224DS1.PDF
U3 = SM8103ADC: IC,High Efficiency,3.0A,18V Input Synchronous Step Down Regulator,SM8103ADC,SMD,TSOT23-6, Silergy; Manufacturer: Silergy; Myir P/N: 20103.00083; Part Type: Power Management; Datasheet: SM8103ADC.pdf
U4 = RT8059GJ5: IC,2.8V to 5.5V Input,1.5MHZ,1A Output,Step-down DCDC Converter,SMD,TSOT23-5,Rychip; Manufacturer: Rychip; Myir P/N: 20103.00069; Part Type: Power Management; RP1 Myir P/N: 20103.00006; Datasheet: RY3408 Datasheet V1.0.0.pdf
C66 = CERAMIC_CAPACITOR: Ceramic Capacitor,10uF,16V,+/-20%,X5R,0603,Samsung; Manufacturer: Samsung; Manufacturer P/N: CL10A106MONQNC; Myir P/N: 20401.80062; Part Type: Ceramic Capacitor; Reserve Value: 10uF; Datasheet: Samsung.pdf
J5 = WQ21801-B2180-7F: Connector,Micro SD Card,8Pin,gold flash,Black,-25~85℃,SMT,Foxconn; Manufacturer: Foxconn; Mark: 1; Myir P/N: 21112.00009; Part Type: Card Connector; Datasheet: SD_Foxconn_WQ21801-B2180-7F.pdf
R56 R57 = Resister: Thick Film Resistor,0R,+/-5%,1/16W,-55°C ~ 155°C,SMD,0402,Fenghua; Manufacturer: Fenghua; Manufacturer P/N: RC-02000JT; Myir P/N: 20301.00186; Part Type: Thick Film Resistor; Reserve Value: 0R; Datasheet: FH规格书_2018-07-30.pdf
R59 R60 R62 R63 = Resister: Thick Film Resistor,1K,+/-5%,1/16W,-55°C ~ 155°C,SMD,0402,Fenghua; Manufacturer: Fenghua; Manufacturer P/N: RC-02W102JT; Myir P/N: 20301.80389; Part Type: Thick Film Resistor; Reserve Value: 1K; Datasheet: FHsheet_2018-07-30.PDF
R64 R65 = Resister: Thick Film Resistor,2.2K,+/-5%,1/16W,-55°C ~ 155°C,SMD,0402,Fenghua; Manufacturer: Fenghua; Manufacturer P/N: RC-02W222JT; Myir P/N: 20301.00195; Part Type: Thick Film Resistor; Reserve Value: 2.2K; Datasheet: FH规格书_2018-07-30.pdf
R75 = Resister: Thick Film Resistor,22R,+/-5%,1/16W,-55°C ~ 155°C,SMD,0402,Fenghua; Manufacturer: Fenghua; Manufacturer P/N: RC-02W220JT; Myir P/N: 20301.00187; Part Type: Thick Film Resistor; Reserve Value: 22R; Datasheet: FHsheet_2018-07-30.PDF
SW1 = SWITCH-218-4LPSTR: Switch, Dip Switches SPST 4 switch sections,4 Position,1.27mm Pitch,black housing,white plunger,SMD,CTS; Manufacturer: CTS; Myir P/N: 21203.00002; Part Type: Switch; Datasheet: 218-786217.pdf
C41 C49 C50 = Ceramic_Capacitor: Ceramic Capacitor,10uF,+/-20%,X5R,16V,SMD,0603,Samsung; Manufacturer: Samsung; Manufacturer P/N: CL10A106MO8NQNC; Myir P/N: 20401.80062; Part Type: Ceramic Capacitor; Reserve Value: 10uF; Datasheet: Samsung.pdf
C42 C43 = Ceramic_Capacitor: Ceramic Capacitor,100nF,50V,+/-10%,X7R,0603,Fenghua; Manufacturer: Fenghua; Manufacturer P/N: 0603B104K500NT; Myir P/N: 20401.80129; Part Type: Ceramic Capacitor; Reserve Value: 100nF; Datasheet: FENGHUA-Capacitor.pdf
C46 = CERAMIC_CAPACITOR: Ceramic Capacitor,10uF,+/-20%,X5R,16V,SMD,0603,Samsung; Manufacturer: Samsung; Manufacturer P/N: CL10A106MO8NQNC; Myir P/N: 20401.80062; Part Type: Ceramic Capacitor; Reserve Value: 10uF; Datasheet: Samsung.pdf
C47 C48 = CERAMIC_CAPACITOR: Ceramic Capacitor,1nF,50V,+/-10%,X7R,0402,Fenghua; Manufacturer: Fenghua; Manufacturer P/N: 0402B102K500NT; Myir P/N: 20401.80096; Part Type: Ceramic Capacitor; Reserve Value: 1nF; Datasheet: FENGHUA-Capacitor.pdf
C55 = CERAMIC_CAPACITOR: Ceramic Capacitor,1nF,+/-10%,2kV,X7R,SMD,1206,Fenghua; Manufacturer: Fenghua; Manufacturer P/N: 1206B102K202NT; Myir P/N: 20401.00078; Part Type: Ceramic Capacitor; Reserve Value: 1nF; Datasheet: FENGHUA-Capacitor.pdf
C58 C59 C62 C63 = CERAMIC_CAPACITOR: Ceramic Capacitor,100nF,16V,+/-10%,X7R,0402,Fenghua; Manufacturer: Fenghua; Manufacturer P/N: 0402B104K160NT; Myir P/N: 20401.80188; Part Type: Ceramic Capacitor; Reserve Value: 100nF; Datasheet: FENGHUA-Capacitor.pdf
C64 C65 = Ceramic_Capacitor: Ceramic Capacitor,22pF,50V,+/-5%,C0G,0402,Fenghua; Manufacturer: Fenghua; Manufacturer P/N: 0402CG220J500NT; Myir P/N: 20401.80101; Part Type: Ceramic Capacitor; Reserve Value: 22pF; Datasheet: FENGHUA-Capacitor.pdf
D17 = Schottky_Diode: Diode Schottky,40V 1A ,SMD SOD123L,LRC; Manufacturer: LRC; Myir P/N: 20701.00060; Part Type: Diode; Datasheet: LMBR140T1G.pdf
F2 F3 = Fuse: Polyswitch,16V,0.5A,0.7OHM,1206 SMD,UN; Manufacturer: UN; Myir P/N: 20801.00012; Part Type: Resettable Fuse; RP1 Manufacturer P/N: MF-NSMF075-2; RP1 Myir P/N: 20801.00003; Datasheet: SMD1206 UN.pdf
FB2 = FERRITE_BEAD: Ferrite Bead,220R@100Mhz,1.5A,+/-25%,SMD,0603,Fenghua; Manufacturer: Fenghua; Manufacturer P/N: CBM160808U221T; Myir P/N: 20601.80007; Part Type: Ferrite Bead; Reserve Value: 220R; Datasheet: CBM160808U221T.pdf
J3 = UT12111-B1609-7F: Connector,USB C,24Pin,–25℃~＋85℃,SMT,Foxconn; Manufacturer: Foxconn; Myir P/N: 21107.00017; Part Type: USB Connector; Datasheet: USB_C_Foxconn_UT12111-B1609-7F_.pdf
J4 = UB11121-8FDE-4F: Connector,Double-USB A,Female,Right angle,4Pos,4.13mm,1u”MIN Gold Plate,-55~85℃,Foxconn; Manufacturer: Foxconn; Myir P/N: 21121.00004; Part Type: USB Connector; Datasheet: DUSB_A_Foxconn_UB11121-8FDE-4F.pdf
L4 L5 = Common_Choke: Inductor,Common Choke,90ohm@100MHz,±25%,280mA,0.4ohm,SMD 2*1.2*1.2mm,Sunlord; Manufacturer: Sunlord; Manufacturer P/N: SDCW2012-2-900TF; Myir P/N: 20504.00002; Part Type: Common Inductor; Reserve Value: 90ohm; Datasheet: SDCW2012-2.pdf
Q3 Q4 = P-MOSFET: Mosfet,P-Channel,15V,70OHM,5.6A,SOT23,SMD,YangJie; Manufacturer: YangJie; Myir P/N: 20703.80039; Part Type: Mosfet; RP1 Manufacturer P/N: IRLML6401TRPBF; RP1 Myir P/N: 20703.00005; RP2 Manufacturer P/N: PMV48XPA; RP2 Myir P/N: 20703.00014; Datasheet: YJL2305A.pdf
R36 R38 R39 R43-R46 R48 R52 = RESISTER: Thick Film Resistor,10K,+/-5%,1/16W,-55℃~155℃,SMD,0402,Fenghua; Manufacturer: Fenghua; Manufacturer P/N: RC-02K103JT; Myir P/N: 20301.00199; Part Type: Thick Film Resistor; Reserve Value: 10K; Datasheet: FHsheet-20230524.pdf
R37 = RESISTER: Thick Film Resistor,1K,+/-5%,1/16W,-55℃~155℃,SMD,0402,Fenghua; Manufacturer: Fenghua; Manufacturer P/N: RC-02K102JT; Myir P/N: 20301.80389; Part Type: Thick Film Resistor; Reserve Value: 1K; Datasheet: FHsheet-20230524.pdf
R40-R42 R47 R49 = RESISTER: Thick Film Resistor,0R,+/-5%,1/16W,-55℃~155℃,SMD,0402,Fenghua; Manufacturer: Fenghua; Manufacturer P/N: RC-02000JT; Myir P/N: 20301.00186; Part Type: Thick Film Resistor; Reserve Value: 0R; Datasheet: FHsheet-20230524.pdf
R50 R51 = Resister: Thick Film Resistor,22R,+/-5%,1/16W,-55℃~155℃,SMD,0402,Fenghua; Manufacturer: Fenghua; Manufacturer P/N: RC-02K220JT; Myir P/N: 20301.00187; Part Type: Thick Film Resistor; Reserve Value: 22R; Datasheet: FHsheet-20230524.pdf
R53 = RESISTER: Thick Film Resistor,1M,+/-5%,1/4W,-55°C ~ 155°C,SMD,1206,Fenghua; Manufacturer: Fenghua; Manufacturer P/N: RS-06K105JT; Myir P/N: 20301.00226; Part Type: Thick Film Resistor; Reserve Value: 1M; Datasheet: FHsheet_2018-07-30.PDF
R55 = Resister: Thick Film Resistor,2.2K,+/-5%,1/16W,-55℃~155℃,SMD,0402,Fenghua; Manufacturer: Fenghua; Manufacturer P/N: RC-02K222JT; Myir P/N: 20301.00195; Part Type: Thick Film Resistor; Reserve Value: 2.2K; Datasheet: FHsheet-20230524.pdf
R270 = Resister: Thick Film Resistor,1K,+/-5%,1/16W,-55℃~155℃,SMD,0402,Fenghua; Manufacturer: Fenghua; Manufacturer P/N: RC-02K102JT; Myir P/N: 20301.80389; Part Type: Thick Film Resistor; Reserve Value: 1K; Datasheet: FHsheet-20230524.pdf
U9 = STUSB1600AQTR: IC, Standalone USB Type-CTM controller with high voltage protections,-40 °C up to 105 °C,QFN24 EP 4x4 mm,ST; Manufacturer: ST; Myir P/N: 20113.80004; Part Type: Interface; RP1 Manufacturer P/N: STUSB1602AQTR; RP1 Myir P/N: 20107.00086; Datasheet: STUSB1600AQTR.pdf
U10 = CH334H: IC,4-port USB HUB controller chip,QFN28,SMD,Tube,WCH; Manufacturer: WCH; Myir P/N: 20107.00106; Part Type: Interface; Datasheet: CH334DS1 (3).PDF
Y2 = Crystal_4P: Crystal,12MHz,+/-20ppm,18pF,-40~85°C,4Pin,3225,SMD,SJK; Manufacturer: SJK / SJK; Manufacturer P/N: SJK-7U12000MAH2420B8; Myir P/N: 20901.00031; Part Type: Crystal; RP1 Manufacturer P/N: 7M12000031; RP1 Myir P/N: 20901.00003; Datasheet: 7U12000MAH2420B8.pdf

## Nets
GND: C1.2 C2.2 C3.2 C4.2 C5.2 C6.2 C7.2 C8.2 C9.2 C12.2 C13.2 C14.1 C15.2 C16.2 C17.2 C20.2 C21.2 C22.2 C23.2 C25.2 C26.2 C27.2 C28.2 C29.2 C30.2 C31.2 C32.2 C33.2 C34.2 C35.2 C36.2 C37.2 C38.2 C39.2 C40.2 C41.2 C42.2 C44.2 C45.2 C46.2 C47.2 C48.2 C49.2 C50.2 C51.2 C52.2 C53.2 C54.2 C55.1 C56.2 C57.2 C58.2 C59.2 C60.2 C61.2 C62.2 C63.2 C64.2 C65.2 C66.2 C67.2 C176.2 C177.2 C178.2 D1.1 D2.1 D3.1 D4.1 D5.1 D6.1 D7.1 D8.1 D9.1 D10.1 D11.1 D12.1 D13.1 D14.1 D15.1 D16.1 D18.1 D19.1 D20.1 D21.1 D22.1 D23.1 D24.1 J1.A1(GND) J1.A12(GND) J1.B1(GND) J1.B12(GND) J2.8 J2.10 J2.13 J2.16 J2.19 J2.22 J2.25 J2.26 J3.A1(GND1) J3.A12(GND2) J3.B1(GND4) J3.B12(GND3) J4.A4(GND) J4.B4(GND) J5.6(VSS) J5.10(GND) J5.11(Sh1) J5.12(Sh2) J5.13(Sh3) R4.2 R5.1 R6.1 R9.1 R12.2 R14.2 R18.2 R19.2 R45.2 R48.2 R49.2 R52.2 R53.2 R62.2 R63.2 R64.2 R65.2 R270.1 TP2.1(TP) U2.6(NMOS#) U2.14(ISP) U2.15(ISN) U2.21(GND) U3.2(GND) U4.2(GND) U5.B1(GND_CH1) U5.B2(GND_CH2) U6.B1(GND_CH1) U6.B2(GND_CH2) U6.B3(GND_CH3) U7.11(GND) U8.2(GND) U9.10(GND) U9.22(VSYS) U9.25(EP) U10.29(GND29) Y1.2(GND) Y2.2 Y2.4 ; also on sheet 8 9 10 11 12 13 14 15
GND_EARTH: C14.2 C55.2 J1.SH1 J1.SH2 J1.SH3 J1.SH4 J3.SH1 J3.SH2 J3.SH3 J3.SH4 J3.SH5 J3.SH6 J4.1(BODY1) J4.2(BODY2) J4.3(BODY3) J4.4(BODY4) R4.1 R53.1 ; also on sheet 8 10 15
VDD_1V8: C24.2 C25.1 C26.1 C27.1 C35.1 C36.1 C37.1 C38.1 FB1.2 L3.2 R17.2 R26.1 R27.1 R28.1 R29.1 R30.1 R31.1 R34.1 TP4.1(TP) U7.2(VCCA) U8.3(VCCA) ; also on sheet 8 11
VDD_3V3: C19.1 C20.1 C21.1 C22.1 C23.1 C33.1 C34.1 C39.1 C40.1 C60.1 C61.1 C62.1 C63.1 L2.2 R11.1 R32.1 R33.1 R39.1 R43.1 R44.1 R46.1 R54.1 R57.2 R67.2 TP3.1(TP) U7.19(VCCB) U8.7(VCCB) U10.14(VDD33) U10.21(VDD33) U10.28(VDD33) ; also on sheet 8 9 10 11 12 13
VDD_5V: C3.1 C4.1 C5.1 C6.1 C7.1 C8.1 C9.1 C15.1 C16.1 C17.1 C28.1 C31.1 C32.1 C41.1 C42.1 C46.1 C56.1 C57.1 C58.1 C59.1 D1.2 D17.1 F1.2 F2.1 F3.2 J2.1 Q3.3(D) R10.1 R16.1 R38.1 TP1.1(TP) U3.5(IN) U4.4(VIN) U9.24(VDD) ; also on sheet 8 12 14
VDD_5V_VBUS: C51.1 C52.1 C53.1 C54.1 F2.2 F3.1 J4.A1(VCC) J4.B1(VCC) R55.1 T8.1(TP)
VDD_LDO: C13.1 R3.2 U2.7(VDD)
VDD_SD: C66.1 C67.1 J5.4(VCC) R66.1 R67.1 R68.1 R69.1 R70.1 R71.1 R72.1 R73.1 R74.1
VDD_SOM_3V3OUT: R56.2 R66.2 ; also on sheet 12 14
VDD_USB0_VBUS: C44.1 C45.1 D6.2 FB2.2 J3.A4(VBUS1) J3.A9(VBUS2) J3.B4(VBUS4) J3.B9(VBUS3) R35.2
VDD_VBUS: C1.1 C2.1 J1.A4(VBUS) J1.A9(VBUS) J1.B4(VBUS) J1.B9(VBUS) U1.2 U2.2(VBUS)
VDD_VBUS_5V: F1.1 U1.3
CARRIER_PWR_ON: R8.1 R15.1 ; also on sheet 14
CC1: D3.2 J1.A5(CC1) R5.2 U2.11(CC1)
CC2: D2.2 J1.B5(CC2) R6.2 U2.10(CC2)
CSI_CLK_N: J2.18 U6.A2(CH1_IN-)
CSI_CLK_P: J2.17 U6.A1(CH1_IN+)
CSI_DATA0_N: J2.24 U6.A6(CH3_IN-)
CSI_DATA0_P: J2.23 U6.A5(CH3_IN+)
CSI_DATA1_N: J2.21 U6.A4(CH2_IN-)
CSI_DATA1_P: J2.20 U6.A3(CH2_IN+)
CSI_DATA2_N: J2.15 U5.A4(CH2_IN-)
CSI_DATA2_P: J2.14 U5.A3(CH2_IN+)
CSI_DATA3_N: J2.12 U5.A2(CH1_IN-)
CSI_DATA3_P: J2.11 U5.A1(CH1_IN+)
HOST1_USB_DM: L5.2 U10.3(DM1)
HOST1_USB_DP: L5.3 U10.4(DP1)
HOST2_USB_DM: L4.2 U10.6(DM2)
HOST2_USB_DP: L4.3 U10.7(DP2)
OVCUR#: R55.2 T22.1(TP) U10.24(OVCUR2#) U10.25(OVCUR1#)
PWREN#: R270.2 U10.8(PWREN#)
RESET#: R54.2 U10.17(RESET#/CDP)
RIIC0_SCL_1V8: R25.1 R28.2 T4.1(TP) U7.3(A2) ; also on sheet 8
RIIC0_SDA_1V8: R24.1 R27.2 T2.1(TP) U7.1(A1) ; also on sheet 8
RZ_CSI_CLK_N: U6.C2(CH1_OUT-) ; also on sheet 14
RZ_CSI_CLK_P: U6.C1(CH1_OUT+) ; also on sheet 14
RZ_CSI_DATA0_N: U6.C6(CH3_OUT-) ; also on sheet 14
RZ_CSI_DATA0_P: U6.C5(CH3_OUT+) ; also on sheet 14
RZ_CSI_DATA1_N: U6.C4(CH2_OUT-) ; also on sheet 14
RZ_CSI_DATA1_P: U6.C3(CH2_OUT+) ; also on sheet 14
RZ_CSI_DATA2_N: U5.C4(CH2_OUT-) ; also on sheet 14
RZ_CSI_DATA2_P: U5.C3(CH2_OUT+) ; also on sheet 14
RZ_CSI_DATA3_N: U5.C2(CH1_OUT-) ; also on sheet 14
RZ_CSI_DATA3_P: U5.C1(CH1_OUT+) ; also on sheet 14
RZ_DEBUGEN: SW1.5(ON4) ; also on sheet 14
RZ_DISP_DATA20: U7.12(B8) ; also on sheet 14
RZ_MD_BOOT0: SW1.8(ON1) ; also on sheet 14
RZ_MD_BOOT1: R64.1 SW1.7(ON2) ; also on sheet 14
RZ_MD_BOOT2: R65.1 SW1.6(ON3) ; also on sheet 14
RZ_P1_1: R43.2 U9.9(ALERT#) ; also on sheet 14
RZ_P16_1_1V8: U7.9(A8) ; also on sheet 8
RZ_P39_0: U7.17(B3) ; also on sheet 14
RZ_P39_0_1V8: R23.1 R29.2 U7.4(A3)
RZ_P39_1: U7.16(B4) ; also on sheet 14
RZ_P39_1_1V8: J2.6 R30.2 U7.5(A4)
RZ_P39_2: U7.15(B5) ; also on sheet 14
RZ_P39_2_1V8: J2.7 R31.2 U7.6(A5)
RZ_P42_2: U7.14(B6) ; also on sheet 14
RZ_P42_2_1V8: U7.7(A6) ; also on sheet 8
RZ_RIIC0_SCL: R33.2 R44.2 R51.2 T3.1(TP) U7.18(B2) ; also on sheet 8 14
RZ_RIIC0_SDA: R32.2 R46.2 R50.2 T1.1(TP) U7.20(B1) ; also on sheet 8 14
RZ_SD1_CD_N: D24.2 J5.9(CD) R74.2 T13.1(TP) ; also on sheet 14
RZ_SSI1_BCK: U8.1(B2) ; also on sheet 14
RZ_SSI1_BCK_1V8: U8.4(A2) ; also on sheet 8
RZ_SSI1_RCK: U8.8(B1) ; also on sheet 14
RZ_SSI1_RCK_1V8: U8.5(A1) ; also on sheet 8
RZ_SSI1_TXD: U7.13(B7) ; also on sheet 14
RZ_SSI1_TXD_1V8: U7.8(A7) ; also on sheet 8
RZ_USB0_DM: D7.2 J3.A7(DN1) J3.B7(DN2) ; also on sheet 14
RZ_USB0_DP: D8.2 J3.A6(DP1) J3.B6(DP2) ; also on sheet 14
RZ_USB0_OTG_ID: R39.2 R48.1 T5.1(TP) ; also on sheet 14
RZ_USB0_VBUSIN: R35.1 ; also on sheet 14
RZ_USB1_DM: D15.2 U10.1(DMU) ; also on sheet 14
RZ_USB1_DP: D16.2 U10.2(DPU) ; also on sheet 14
SD1_CLK: R75.1 T11.1(TP) ; also on sheet 11
SD1_CMD: D20.2 J5.3(CMD) R70.2 T10.1(TP) ; also on sheet 11
SD1_D0: D22.2 J5.7(DAT0) R72.2 T12.1(TP) ; also on sheet 11
SD1_D1: D23.2 J5.8(DAT1) R73.2 ; also on sheet 11
SD1_D2: D18.2 J5.1(DAT2) R68.2 ; also on sheet 11
SD1_D3: D19.2 J5.2(DAT3) R69.2 T9.1(TP) ; also on sheet 11
USB2CC1: C47.1 R40.2 R41.1 U9.2(CC1)
USB2CC2: C48.1 R42.1 R47.2 U9.4(CC2)
N23563869: J2.4 R24.2
N23563890: J2.5 R25.2
N23565746: J2.2 R23.2
N23725979: C29.1 FB1.1 R20.1 Y1.4(VCC/Vdd)
N23726017: R21.1 Y1.3(OUT/Output)
N23737816: J2.9 R21.2
N24039867: R26.2 U7.10(OE)
N24759045: R60.2 SW1.3(OFF3)
N24759067: R58.2 R62.1 SW1.1(OFF1)
N24759190: R59.2 SW1.2(OFF2)
N24761427: R56.1 R57.1 R58.1 R59.1 R60.1 R61.1
N24944194: D21.2 J5.5(CLK) R71.2 R75.2
N25776699: C30.1 R20.2 Y1.1(EN/Vcont/NC)
N25785637: R61.2 R63.1 SW1.4(OFF4)
N25991714: D5.2 J1.A6(Dp1) J1.B6(Dp2) U2.8(UDP)
N25991722: D4.2 J1.A7(Dn1) J1.B7(Dn2) U2.9(UDM)
N26002192: R3.1 R9.2 U2.1(DRV) U2.19(CFG1)
N26033210: C12.1 R10.2 R12.1 R15.2 U3.4(EN)
N26033282: C18.2 L2.1 U3.6(LX)
N26033286: C18.1 U3.1(BS)
N26033313: C19.2 R11.2 R14.1 U3.3(FB)
N26043102: C24.1 R17.1 R19.1 U4.5(FB)
N26043137: L3.1 U4.3(LX)
N26043190: C178.1 R8.2 R16.2 R18.1 U4.1(EN)
N26059117: C43.1 Q3.1(G) Q4.1(G) R36.2 R37.1
N26059354: D9.2 J3.A5(CC1) R41.2
N26059364: D10.2 J3.B5(CC2) R42.2
N26059408: R51.1 U9.7(SCL)
N26059410: R50.1 U9.8(SDA)
N26059424: C50.1 U9.23(VREG_2V7)
N26059430: R47.1 U9.5(CC2DB)
N26059432: R40.1 U9.1(CC1DB)
N26059441: C43.2 Q3.2(S) Q4.2(S) R36.1
N26059484: C49.1 U9.21(VREG_1V2)
N26059520: R52.1 U9.6(RESET)
N26059554: R38.2 R45.1 U9.3(VCONN)
N26059572: R37.2 U9.20(VBUS_EN_SRC)
N26059598: FB2.1 Q4.3(D) U9.18(VBUS_SENSE)
N26059749: R49.1 U9.13(ADDR0)
N26112798: R34.2 U8.6(OE)
N26137432: C176.1 C177.1 D17.2 U10.27(V5)
N26147104: C64.1 U10.10(XI) Y2.3
N26147108: C65.1 U10.11(XO) Y2.1
N26155524: D11.2 J4.A2(USBHMA) L4.1
N26155536: D12.2 J4.A3(USBHPA) L4.4
N26155544: D14.2 J4.B2(USBHMB) L5.1
N26155546: D13.2 J4.B3(USBHPB) L5.4
N26211804: T20.1(TP) U2.13(CFG2)
N26211815: T21.1(TP) U2.12(CFG3)
N26218647: T7.1(TP) U9.12(ATTACH)
N26218648: T6.1(TP) U9.11(VBUS_VALID)

Not connected (* = marked no-connect by the designer): J1 A8(SBU1) B8(SBU2); J2 3*; J3 A2(SSTXP1) A3(SSTXN1) A8(SBU1) A10(SSRXN2) A11(SSRXP2) B2(SSTXP2) B3(SSTXN2) B8(SBU2) B10(SSRXN1) B11(SSRXP1); U1 1*; U2 3(NC3) 4(NC4) 5(GATE) 16(NC16) 17(NC17) 18(NC18) 20(NC20); U9 14(DEBUG1) 15(DEBUG2) 16(NC) 17(A_B_SIDE) 19(VBUS_EN_SNK); U10 5(NC5)* 9(NC9)* 12(DM3)* 13(DP3)* 15(DM4)* 16(DP4)* 18(LED3/SCL)* 19(OVCUR4#) 20(OVCUR3#) 22(PSELF)* 23(PGANG)* 26(LED4/SDA)*

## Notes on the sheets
sheet 1
- Index
- VERSION HISTORY
- Revision
- Description
- Date
- Drawn
- Checked
- Approved
- 1.  Cover
  2.  Block Diagram
  3.  Power Tree
  4.  Power Supply
  5.  MIPI CSI
  6.  USB OTG & Host
  7.  SD & BOOT
  8.  DSI - HDMI & LVDS
  9.  Audio
  10. ENET0 & ENET1
  11. WIFI & BT
  12. PH-RPI & KEY & RTC
  13. Debug
  14. MYC Connector
  15. Mechanical
- V01
- Initial Edition
- 2023-11-02
- Dana
- V10
- 1、R1,Q1,C10,C11,R2,Q2 ,R16 delete
  2、Add R12 10K，C178 100nF
- 2023-12-25
- Dana
sheet 4
- ONOFF KEY
- Imax=3A,Iload=2A
- 3.31V
- FB=0.6V
- Imax=1A,1.8V
sheet 5
- MIPI CSI
- MY CAM003M VDDIO =1.8V
- I2C/GPIO 1.8V
- MCAM_EN
- 1: Active
- MCAM_RST
- MCAM_PWDN
- Level-Shifting
- Level-Shifting
sheet 6
- USB C （OTG/DRP）
- RZ_USB0_VBUSIN hvae been connected to 3.3V  on SOM
- USB TYPE-C
- IRQ3
- USB HOST
- USB HUB
sheet 7
- BOOT SEL
- 10K Pull up on SOM        S0    1
- 10K Pull down on SOM      S1
- 10K Pull down on SOM      S2
- 10K Pull up on SOM        S3
- Boot from eMMC  by default on SOM
- Silkscreen information is
  on the carried board
- BOOT MODE
  MD_BOOT[2:1:0]
- Interface
- Boot Device
- S2 S1 S0
- Boot Device
- S2 S1 S0
- Boot Device
- 001
- SDHI0
- 1.8V eMMC
- 000
- 1.8V eMMC
- S3
- Mode
- 000
- eMMC
- 0
- JTAG
- 011
- SPIBSC
- 1.8V QSPI
- 010
- 1.8V QSPI
- 1
- Normal
- 100
- Download
- 100
- SPIBSC
- 3.3V QSPI
- 101
- 3.3V QSPI
- 101
- SCIF0
- Downloading
- 100
- Downloading
- Micro SD
